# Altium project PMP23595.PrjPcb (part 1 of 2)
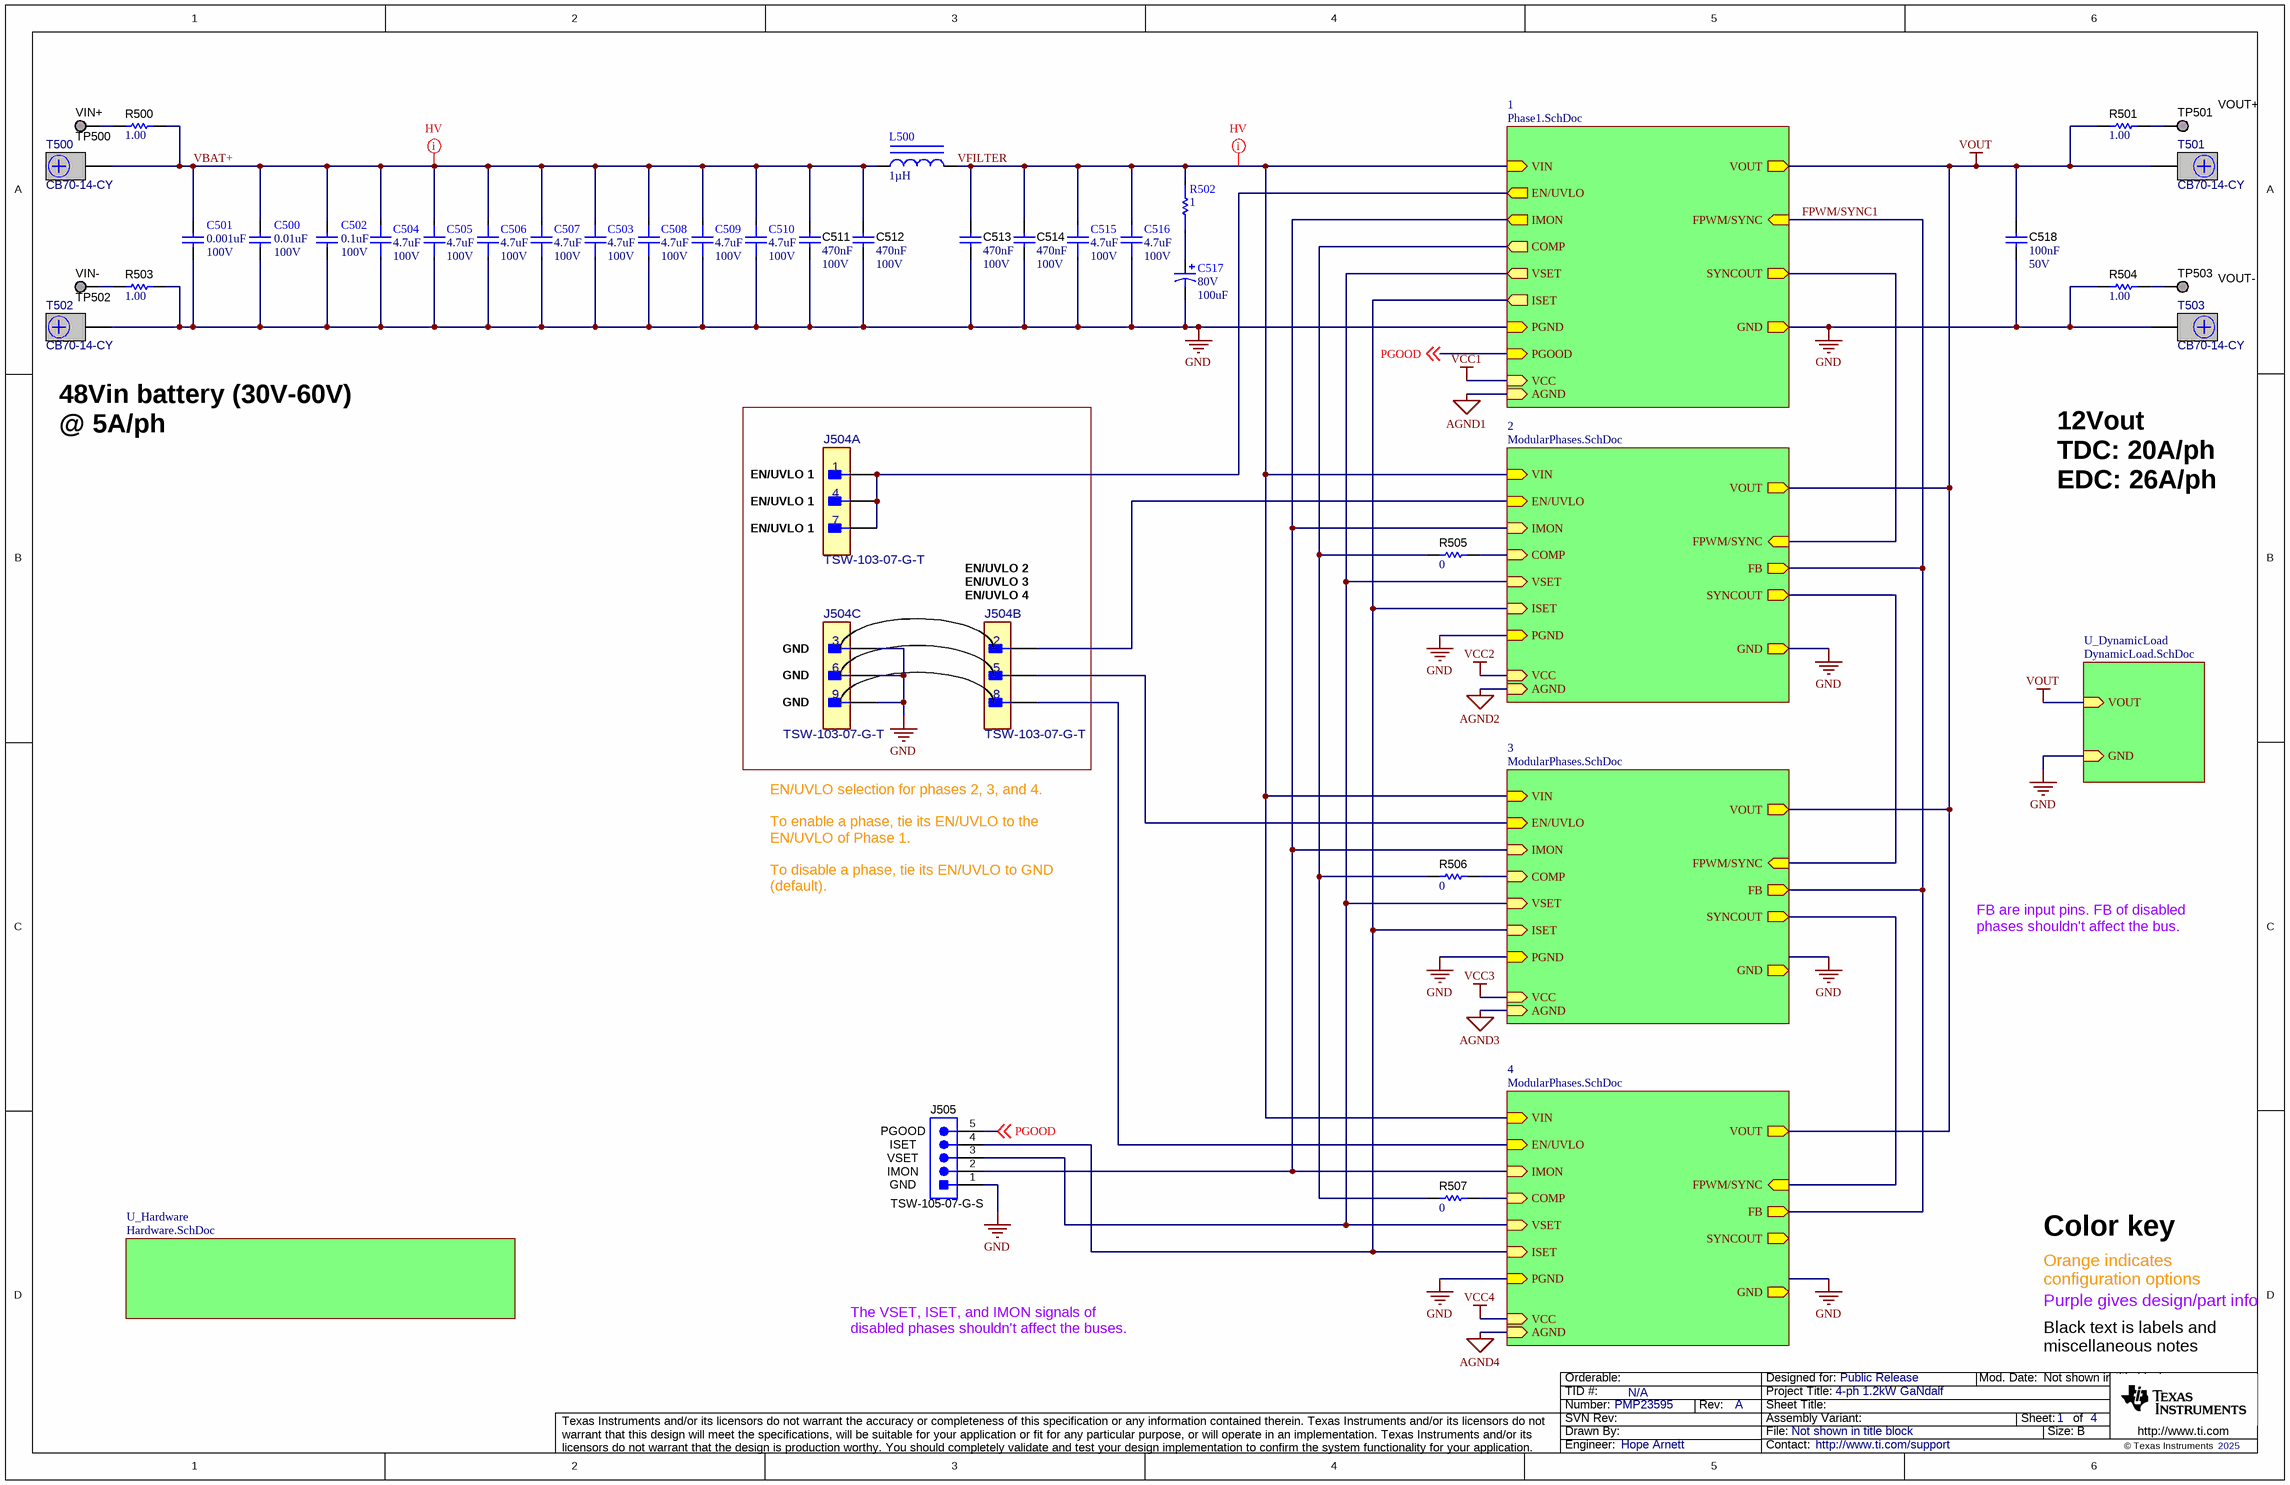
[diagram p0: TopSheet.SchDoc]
CopyrightYear: 2025; PCB_Layout: Hope Arnett; PCB_Rev: A; PRJ_Customer: Public Release; PRJ_Engineer: Hope Arnett; PRJ_Number: PMP23595; PRJ_Title: 4-ph 1.2kW GaNdalf; SCH_Rev: A; TechSupport: http://www.ti.com/support; TID: N/A
5 sheets, 237 parts. Net scope: hierarchical (ports join the sheet entries above them; power ports are global).
Board file: PMP23595.PcbDoc
Sheets:
  TopSheet.SchDoc
    U_Hardware = Hardware.SchDoc
    2 = ModularPhases.SchDoc
    1 = Phase1.SchDoc
    U_DynamicLoad = DynamicLoad.SchDoc
    3 = ModularPhases.SchDoc
    4 = ModularPhases.SchDoc

## Sheet TopSheet.SchDoc
size 431 x 279 mm; Date: Not shown in title block; ApprovedBy: Not shown in title block; CheckedBy: Not shown in title block; Author: Not shown in title block; CompanyName: Not shown in title block; Engineer: Not shown in title block; Organization: Not shown in title block; Address1: Not shown in title block; Address2: Not shown in title block; Address3: Not shown in title block; Address4: Not shown in title block; DocumentNumber: 1; Revision: Use project parameter SCH_Rev; SheetNumber: 1; SheetTotal: 4; PageSetup: Record=PageOptions¦CenterHorizontal=True¦CenterVertical=True¦PrintScale=1.00¦XCorrection=1.00¦YCorrection=1.00¦PrintKind=0¦BorderSize=5000000¦LeftOffset=0¦BottomOffset=0¦Orientation=2¦PaperLength=1000¦PaperWidth=1000¦Scale=100¦PaperSource=15¦PrintQuality=600¦MediaType=1¦DitherType=10¦PaperKind=Letter¦PrintScaleMode=1

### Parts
C500  Value2: 100V  ValueDisplayed: 0.01uF  [0603L]  (hidden comment: GRM188R72A103KA01D)
C501  Cap_F: 0.001uF  VDC_V: 100V  [0603L]  (hidden comment: CGA3E2X7R2A102K080AA)
C502  Value2: 100V  ValueDisplayed: 0.1uF  [0805]  (hidden comment: C0805C104K1RACTU)
C503  ValueDisplayed: 4.7uF  VDC_V: 100V  [FP-GCJ32DC72A475KE01L_1210-MFG]  (hidden comment: GCJ32DC72A475KE01L)
C504  ValueDisplayed: 4.7uF  VDC_V: 100V  [FP-GCJ32DC72A475KE01L_1210-MFG]  (hidden comment: GCJ32DC72A475KE01L)
C505  ValueDisplayed: 4.7uF  VDC_V: 100V  [FP-GCJ32DC72A475KE01L_1210-MFG]  (hidden comment: GCJ32DC72A475KE01L)
C506  ValueDisplayed: 4.7uF  VDC_V: 100V  [FP-GCJ32DC72A475KE01L_1210-MFG]  (hidden comment: GCJ32DC72A475KE01L)
C507  ValueDisplayed: 4.7uF  VDC_V: 100V  [FP-GCJ32DC72A475KE01L_1210-MFG]  (hidden comment: GCJ32DC72A475KE01L)
C508  ValueDisplayed: 4.7uF  VDC_V: 100V  [FP-GCJ32DC72A475KE01L_1210-MFG]  (hidden comment: GCJ32DC72A475KE01L)
C509  ValueDisplayed: 4.7uF  VDC_V: 100V  [FP-GCJ32DC72A475KE01L_1210-MFG]  (hidden comment: GCJ32DC72A475KE01L)
C510  ValueDisplayed: 4.7uF  VDC_V: 100V  [FP-GCJ32DC72A475KE01L_1210-MFG]  (hidden comment: GCJ32DC72A475KE01L)
C511  Cap_F: 470nF  VDC_V: 100V  [0805L]  (hidden comment: GRM21BR72A474KA73L)
C512  Cap_F: 470nF  VDC_V: 100V  [0805L]  (hidden comment: GRM21BR72A474KA73L)
C513  Cap_F: 470nF  VDC_V: 100V  [0805L]  (hidden comment: GRM21BR72A474KA73L)
C514  Cap_F: 470nF  VDC_V: 100V  [0805L]  (hidden comment: GRM21BR72A474KA73L)
C515  ValueDisplayed: 4.7uF  VDC_V: 100V  [FP-GCJ32DC72A475KE01L_1210-MFG]  (hidden comment: GCJ32DC72A475KE01L)
C516  ValueDisplayed: 4.7uF  VDC_V: 100V  [FP-GCJ32DC72A475KE01L_1210-MFG]  (hidden comment: GCJ32DC72A475KE01L)
C517  VDC_V: 80V  ValueDisplayed: 100uF  [SM_RADIAL_H13]  (hidden comment: EEV-FK1K101Q)
C518  Cap_F: 100nF  VDC_V: 50V  [0603L]  (hidden comment: 06035C104KAZ2A)
J504  TSW-103-07-G-T  [FP-TSW-103-07-G-T_HDR9-MFG]  (parts A,B,C of 3)
J505  TSW-105-07-G-S  [TSW-105-07-X-S]
L500  ValueDisplayed: 1µH  [VCHA105D]  (hidden comment: VCHA105D-1R0MS6)
R500  ValueDisplayed: 1.00  [0603L]  (hidden comment: CRCW06031R00FKEA)
R501  ValueDisplayed: 1.00  [0603L]  (hidden comment: CRCW06031R00FKEA)
R502  value 1  [FP-RCL12251R00FKEG_2512-MFG]  (hidden comment: RCL12251R00FKEG)
R503  ValueDisplayed: 1.00  [0603L]  (hidden comment: CRCW06031R00FKEA)
R504  ValueDisplayed: 1.00  [0603L]  (hidden comment: CRCW06031R00FKEA)
R505  ValueDisplayed: 0  [0402L]  (hidden comment: RK73Z1ETTP)
R506  ValueDisplayed: 0  [0402L]  (hidden comment: RK73Z1ETTP)
R507  ValueDisplayed: 0  [0402L]  (hidden comment: RK73Z1ETTP)
T500  CB70-14-CY  [CB70-14-CY]
T501  CB70-14-CY  [CB70-14-CY]
T502  CB70-14-CY  [CB70-14-CY]
T503  CB70-14-CY  [CB70-14-CY]
TP500  VIN+  [Keystone_5019]
TP501  VOUT+  [Keystone_5019]
TP502  VIN-  [Keystone_5019]
TP503  VOUT-  [Keystone_5019]

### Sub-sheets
1 = Phase1.SchDoc: VIN (in), PGND (in), VOUT (out), GND (out), EN/UVLO (out), SYNCOUT (out), COMP (out), AGND (in), VCC (in), IMON (out), ISET (out), VSET (out), FPWM/SYNC (in), PGOOD (in)
2 = ModularPhases.SchDoc: VIN (in), PGND (in), VOUT (out), GND (out), FPWM/SYNC (in), SYNCOUT (out), COMP (in), AGND (in), VCC (in), EN/UVLO (in), IMON (in), VSET (in), ISET (in), FB (out)
3 = ModularPhases.SchDoc: VIN (in), PGND (in), VOUT (out), GND (out), FPWM/SYNC (in), SYNCOUT (out), COMP (in), AGND (in), VCC (in), EN/UVLO (in), IMON (in), VSET (in), ISET (in), FB (out)
4 = ModularPhases.SchDoc: VIN (in), PGND (in), VOUT (out), GND (out), FPWM/SYNC (in), SYNCOUT (out), COMP (in), AGND (in), VCC (in), EN/UVLO (in), IMON (in), VSET (in), ISET (in), FB (out)
U_DynamicLoad = DynamicLoad.SchDoc: VOUT (in), GND (in)
U_Hardware = Hardware.SchDoc: no entries

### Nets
AGND1: sheet 2/AGND, sheet 1/AGND, sheet 3/AGND, sheet 4/AGND  [also labelled AGND2, AGND3, AGND4]
GND: C500.1 C501.2 C502.2 C503.1 C504.1 C505.1 C506.1 C507.1 C508.1 C509.1 C510.1 C511.2 C512.2 C513.2 C514.2 C515.1 C516.1 C517.2(-) C518.2 J504.3 J504.6 J504.9 J505.1 R503.2 R504.1 T502.1 T503.1 ; sheet 2/PGND, sheet 2/GND, sheet 1/PGND, sheet 1/GND, sheet U_DynamicLoad/GND, sheet 3/PGND, sheet 3/GND, sheet 4/PGND, sheet 4/GND
VCC1: sheet 2/VCC, sheet 1/VCC, sheet 3/VCC, sheet 4/VCC  [also labelled VCC2, VCC3, VCC4]
VFILTER: C513.1 C514.1 C515.2 C516.2 L500.2 R502.2 ; sheet 2/VIN, sheet 1/VIN, sheet 3/VIN, sheet 4/VIN
VOUT: C518.1 R501.1 T501.1 ; sheet 2/VOUT, sheet 1/VOUT, sheet U_DynamicLoad/VOUT, sheet 3/VOUT, sheet 4/VOUT
COMP: R505.2 R506.2 R507.2 ; sheet 1/COMP
COMP: R507.1 ; sheet 4/COMP  [a separate net that carries the same name]
COMP: R506.1 ; sheet 3/COMP  [a separate net that carries the same name]
COMP: R505.1 ; sheet 2/COMP  [a separate net that carries the same name]
EN/UVLO: J504.1 J504.4 J504.7 ; sheet 1/EN/UVLO
EN/UVLO: J504.2 ; sheet 2/EN/UVLO  [a separate net that carries the same name]
EN/UVLO: J504.5 ; sheet 3/EN/UVLO  [a separate net that carries the same name]
EN/UVLO: J504.8 ; sheet 4/EN/UVLO  [a separate net that carries the same name]
FPWM/SYNC: sheet 2/FPWM/SYNC, sheet 1/SYNCOUT
FPWM/SYNC: sheet 2/SYNCOUT, sheet 3/FPWM/SYNC  [a separate net that carries the same name]
FPWM/SYNC: sheet 3/SYNCOUT, sheet 4/FPWM/SYNC  [a separate net that carries the same name]
FPWM/SYNC1: sheet 2/FB, sheet 1/FPWM/SYNC, sheet 3/FB, sheet 4/FB
IMON: J505.2 ; sheet 2/IMON, sheet 1/IMON, sheet 3/IMON, sheet 4/IMON
ISET: J505.4 ; sheet 2/ISET, sheet 1/ISET, sheet 3/ISET, sheet 4/ISET
PGOOD: J505.5 ; off-sheet PGOOD, sheet 1/PGOOD
VBAT+: C500.2 C501.1 C502.1 C503.2 C504.2 C505.2 C506.2 C507.2 C508.2 C509.2 C510.2 C511.1 C512.1 L500.1 R500.2 T500.1
VSET: J505.3 ; sheet 2/VSET, sheet 1/VSET, sheet 3/VSET, sheet 4/VSET
NetC517_1: C517.1(+) R502.1
NetR500_1: R500.1 TP500.1
NetR501_2: R501.2 TP501.1
NetR503_1: R503.1 TP502.1
NetR504_2: R504.2 TP503.1

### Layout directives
net class HV: VBAT+, VFILTER

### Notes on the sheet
- (near T502) 48Vin battery (30V-60V) @ 5A/ph
- (near J504) EN/UVLO 1
- 12Vout
  TDC: 20A/ph
  EDC: 26A/ph
- EN/UVLO 2
- EN/UVLO 3
- (near J504) EN/UVLO 4
- (near J504) GND
- EN/UVLO selection for phases 2, 3, and 4.
  To enable a phase, tie its EN/UVLO to the EN/UVLO of Phase 1.
  To disable a phase, tie its EN/UVLO to GND (default).
- FB are input pins. FB of disabled phases shouldn't affect the bus.
- (near J505) IMON
- (near J505) VSET
- (near J505) ISET
- (near J505) PGOOD
- (near J505) GND
- Orange indicates configuration options
- Color key
- The VSET, ISET, and IMON signals of disabled phases shouldn't affect the buses.
- Purple gives design/part info
- Black text is labels and miscellaneous notes

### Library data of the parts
C500 = CMP-0007468-5: CAP, CERM, 0.01 uF, 100 V, +/- 10%, X7R, 0603; Manufacturer: MuRata; TaMin_C: -55°C; Polarized: N; SizeAreaWB_mm2: 4.68; Value1: Unknown; U/M: EA; Value: 0.01uF; TaMax_C: 125°C; SizeZ_mm: 1; SizeX_mm: 1.6; SizeY_mm: 0.8; Cap_Case: 0603; SizeArea_mm2: 1.28; Cap_F: 10nF; AEC Category: Q200
C501 = CMP-0007081-4: CAP, CERM, 1000 pF, 100 V, +/- 10%, X7R, AEC-Q200 Grade 1, 0603; Manufacturer: TDK; TaMin_C: -55°C; ESR_ohm: 1.9714; Polarized: N; SizeAreaWB_mm2: 4.68; Value1: 1.97137 ohm; U/M: EA; Value: 1000pF; TaMax_C: 125°C; SizeZ_mm: 1; SizeX_mm: 1.6; SizeY_mm: 0.8; Cap_Case: 0603; SizeArea_mm2: 1.28; AEC Qualified: Y; IRMS_A: 305.705mA; AEC Category: Q200
C502 = CMP-0007722-2: CAP, CERM, 0.1 uF, 100 V, +/- 10%, X7R, 0805; Manufacturer: Kemet; TaMin_C: -55°C; ESR_ohm: 64m; Polarized: N; SizeAreaWB_mm2: 6.75; Value1: 0.064 ohm; U/M: EA; Value: 0.1uF; TaMax_C: 125°C; SizeZ_mm: 1.45; SizeX_mm: 2; SizeY_mm: 1.25; SizeArea_mm2: 2.5; Cap_F: 100nF; IRMS_A: 1.64A; AEC Category: Q200
C503-C510 C515 C516 = CMP-0093675-1: 4.7uF ±10% 100V Ceramic Capacitor X7S 1210 (3225 Metric); Manufacturer: Murata; Value: 4.7µF; AEC Qualified: Yes; TempCo: 22%; SizeZ_mm: 2.3mm; AEC Grade: Grade 1
C511-C514 = CMP-0008374-2: CAP, CERM, 0.47 uF, 100 V, +/- 10%, X7R, 0805; Manufacturer: MuRata; TaMin_C: -55°C; Polarized: N; SizeAreaWB_mm2: 6.75; Value1: Unknown; U/M: EA; Value: 0.47uF; TaMax_C: 125°C; SizeZ_mm: 1.45; SizeX_mm: 2; SizeY_mm: 1.25; Cap_Case: 0805; SizeArea_mm2: 2.5; AEC Category: Q200
C517 = CMP-0011216-2: CAP, AL, 100 uF, 80 V, +/- 20%, 0.32 ohm, AEC-Q200 Grade 2, SMD; Manufacturer: Panasonic; TaMin_C: -55°C; ESR_ohm: 0.32; Polarized: Y; SizeAreaWB_mm2: 263.5; U/M: EA; Value: 100uF; TaMax_C: 105°C; SizeZ_mm: 13.5; SizeX_mm: 15; Cap_Case: H13; SizeArea_mm2: 202.5; CompType: Capacitor; Cap_F: 100µF; IRMS_A: 500mA; AEC Grade: 2; AEC Category: Q200
C518 = CMP-0079095-1: CAP, CERM, 0.1 µF, 50 V,+/- 10%, X7R, AEC-Q200 Grade 1, 0603; Manufacturer: AVX; SizeAreaWB_mm2: 4.68; SizeArea_mm2: 1.28; AEC Qualified: Y; AEC Category: Q200; Value: 0.1uF; TaMax_C: 125°C; SizeZ_mm: 1; Polarized: N; TaMin_C: -55°C; SizeY_mm: 0.8; U/M: EA; SizeX_mm: 1.6; Cap_Case: 0603; ValueDisplayed: 0.1µF
J504 = CMP-0090263-1: Connector Header Through Hole 9 position 0.100" (2.54mm); Manufacturer: Samtec; Conn Gender: Male; AEC Qualified: No; Conn Orientation: Straight; Row_Count: 3; SizeZ_mm: 8.64mm; ContactFinish: Gold,Nickel
J505 = CMP-0075411-1: Header, 100mil, 5x1, Gold, TH; Manufacturer: Samtec; Pitch_mm: 2.54; Cert_VDE: N; Gender: Male; Cert_CSA: Y; Voltage_V: 550V; Green_REACh: Passed; Current_A: 6.3A; CT: False; Green_Lifecycle: Active; Row_Count: 1; CNHeader: True
L500 = CMP-0086238-1: Inductor, 1 µH, 30 A, 0.00276 ohm, AEC-Q200 Grade 0, SMD; Manufacturer: Cyntec; AEC Category: Q200; AEC Grade: 0; Value: 1uH; AEC Qualified: Y; Irms: 30A @ 40C rise; Isat: 37A @ 30% inductance drop; DCR_ohm: 2.76m; SizeX_mm: 10.85; Imax_A: 30A; SizeArea_mm2: 108.5; SizeZ_mm: 5.4; SizeAreaWB_mm2: 154.2; SizeY_mm: 10
R500 R501 R503 R504 = CMP-0022170-4: RES, 1.00, 1%, 0.1 W, AEC-Q200 Grade 0, 0603; Manufacturer: Vishay-Dale; Power_W: 100mW; TempCo: 100 ppm/C; Value_Code: 1R00; Value: 1.00; EIA_Code: E96; Res_ohm: 1; SizeX_mm: 1.6; SizeY_mm: 0.8; Value2: 0.1W; SizeArea_mm2: 1.28; AEC Qualified: Y; VDC_V: 75V; AEC Category: Q200; AEC Grade: 0
R502 = CMP-0084352-2: 1 Ohms ±1% 2W Chip Resistor Wide 2512 (6432 Metric), 1225 Automotive AEC-Q200 Thick Film; Manufacturer: Vishay Dale; SizeZ_mm: 0.8mm; Symbol Name: SYM-RCL12251R00FKEG; TempCo: 100ppm/°C; VDC_V: 200V; AEC Qualified: Yes; AEC Grade: Grade 0
R505-R507 = CMP-0027007-2: RES, 0, 5%, 0.063 W, AEC-Q200 Grade 0, 0402; Manufacturer: KOA Speer; Power_W: 63mW; TempCo: ppm/C; Value_Code: 0000; U/M: EA; Value: 0; EIA_Code: E24; SizeX_mm: 1; SizeY_mm: 0.5; SizeZ_mm: 0.6; Value2: 0.063W; AEC Qualified: Y; AEC Category: Q200
T500-T503 = CMP-0055443-2: Terminal 90A Lug; Manufacturer: Panduit; Green_Lifecycle: Not Set; Cert_CULUS: Y; Green_REACh: Incomplete; Voltage_V: 600V; CompType: Screw Terminal; ContactFinish: Copper
TP500-TP503 = CMP-0055162-1: Test Point, Miniature, SMT; Manufacturer: Keystone; PartNumber: 5019; CNHeader: FALSE; Green_Lifecycle: Active; Green_REACh: Passed; CT: TRUE

## Sheet Hardware.SchDoc
size 431 x 279 mm; Date: Not shown in title block; ApprovedBy: Not shown in title block; CheckedBy: Not shown in title block; Author: Not shown in title block; CompanyName: Not shown in title block; Engineer: Not shown in title block; Organization: Not shown in title block; Address1: Not shown in title block; Address2: Not shown in title block; Address3: Not shown in title block; Address4: Not shown in title block; DocumentNumber: 4; Revision: Use project parameter SCH_Rev; SheetNumber: 4; SheetTotal: 4; PageSetup: Record=PageOptions¦CenterHorizontal=True¦CenterVertical=True¦PrintScale=1.00¦XCorrection=1.00¦YCorrection=1.00¦PrintKind=0¦BorderSize=5000000¦LeftOffset=0¦BottomOffset=0¦Orientation=2¦PaperLength=1000¦PaperWidth=1000¦Scale=100¦PaperSource=15¦PrintQuality=600¦MediaType=1¦DitherType=10¦PaperKind=Letter¦PrintScaleMode=1
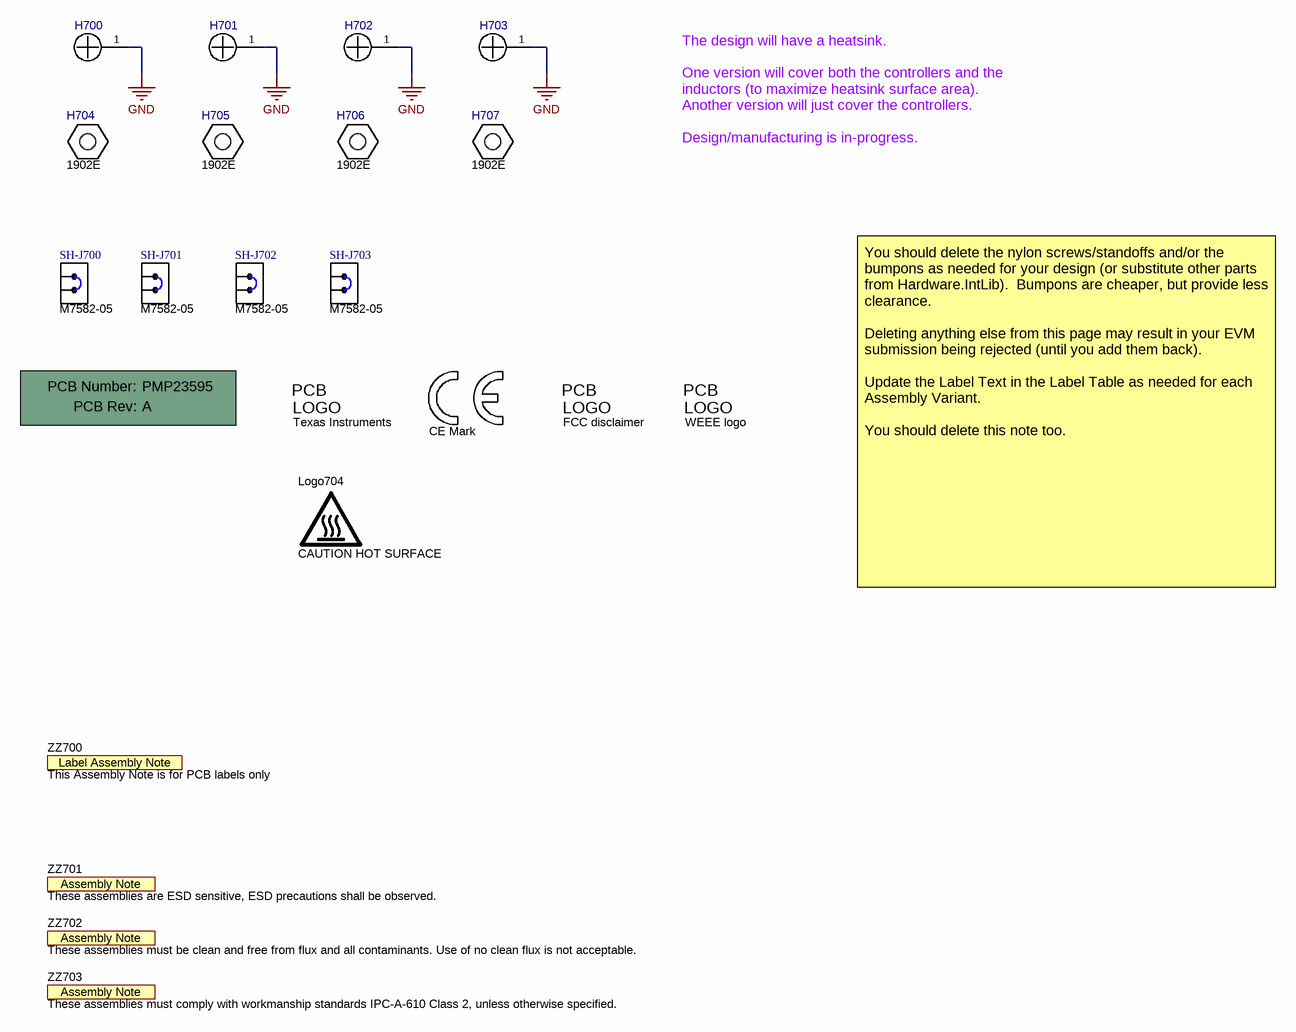
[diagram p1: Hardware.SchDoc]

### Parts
!PCB700  Printed Circuit Board  (value not drawn)  (mechanical)
H700  NY PMS 440 0025 PH  [NY PMS 440 0025 PH]  (value not drawn)
H701  NY PMS 440 0025 PH  [NY PMS 440 0025 PH]  (value not drawn)
H702  NY PMS 440 0025 PH  [NY PMS 440 0025 PH]  (value not drawn)
H703  NY PMS 440 0025 PH  [NY PMS 440 0025 PH]  (value not drawn)
H704  1902E  [Keystone_1902E]
H705  1902E  [Keystone_1902E]
H706  1902E  [Keystone_1902E]
H707  1902E  [Keystone_1902E]
Logo700  CE Mark  [CE_Mark_5mm]  (no BOM)
Logo701  Texas Instruments  [TI_Stacked_Overlay_Small]  (no BOM)
Logo702  FCC disclaimer  [FCC_disclaimer]  (no BOM)
Logo703  WEEE logo  [WEEE_Minimum]  (no BOM)
Logo704  CAUTION HOT SURFACE  [IEC_HotSurface_Small]  (no BOM)
SH-J700  M7582-05  [Harwin_M7582-05]
SH-J701  M7582-05  [Harwin_M7582-05]
SH-J702  M7582-05  [Harwin_M7582-05]
SH-J703  M7582-05  [Harwin_M7582-05]
ZZ700  This Assembly Note is for PCB labels only  [AssemblyNoteLabel]  (no BOM)
ZZ701  These assemblies are ESD sensitive, ESD precautions shall be observed.  [AssemblyNote]  (no BOM)
ZZ702  These assemblies must be clean and free from flux and all contaminants. Use of no clean flux is not acceptable.  [AssemblyNote]  (no BOM)
ZZ703  These assemblies must comply with workmanship standards IPC-A-610 Class 2, unless otherwise specified.  [AssemblyNote]  (no BOM)

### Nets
GND: H700.1 H701.1 H702.1 H703.1

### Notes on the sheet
- The design will have a heatsink.
  One version will cover both the controllers and the inductors (to maximize heatsink surface area). Another version will just cover the controllers.
  Design/manufacturing is in-progress.
- You should delete the nylon screws/standoffs and/or the bumpons as needed for your design (or substitute other parts from Hardware.IntLib).  Bumpons are cheaper, but provide less clearance.
  Deleting anything else from this page may result in your EVM submission being rejected (until you add them back).
  Update the Label Text in the Label Table as needed for each Assembly Variant.
  You should delete this note too.

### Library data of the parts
!PCB700 = CMP-0003618-2: Manufacturer: Any; PartNumber: PMP23595
H700-H703 = CMP-0003617-1: Machine Screw, Round, #4-40 x 1/4, Nylon, Philips panhead; Manufacturer: B&F Fastener Supply; CompType: Hardware
H704-H707 = CMP-0003611-1: Standoff, Hex, 1"L #4-40 Nylon; Manufacturer: Keystone; CompType: Hardware
Logo700 = CMP-0074844-1: SymbolCreator: a0412235
Logo701 = CMP-0074838-1: Texas Instrument Corporate Signature; SymbolCreator: a0412235; Lib Reference: TI_Logo; Library Reference: Logo
Logo702 = CMP-0074847-1: FCC_disclaimer; Library Reference: Logo
Logo703 = CMP-0074769-1
Logo704 = CMP-0074837-2: IEC 61010-1 Hot Surface Warning; Manufacturer: Texas Instruments; CompType: IC; AEC Category: Q200; SymbolCreator: a0412235
SH-J700-SH-J703 = CMP-0078738-1: Single Operation 2.54mm Pitch Open Top Jumper Socket; Manufacturer: Harwin
ZZ700 = CMP-0003616-3
ZZ701 = CMP-0077236-1
ZZ702 = CMP-0077237-1
ZZ703 = CMP-0077238-1

## Sheet ModularPhases.SchDoc
size 431 x 279 mm; Date: Not shown in title block; ApprovedBy: Not shown in title block; CheckedBy: Not shown in title block; Author: Not shown in title block; CompanyName: Not shown in title block; Engineer: Not shown in title block; Organization: Not shown in title block; Address1: Not shown in title block; Address2: Not shown in title block; Address3: Not shown in title block; Address4: Not shown in title block; DocumentNumber: 3; Revision: Use project parameter SCH_Rev; SheetNumber: 3; SheetTotal: 4; PageSetup: Record=PageOptions¦CenterHorizontal=True¦CenterVertical=True¦PrintScale=1.00¦XCorrection=1.00¦YCorrection=1.00¦PrintKind=0¦BorderSize=5000000¦LeftOffset=0¦BottomOffset=0¦Orientation=2¦PaperLength=1000¦PaperWidth=1000¦Scale=100¦PaperSource=15¦PrintQuality=600¦MediaType=1¦DitherType=10¦PaperKind=Letter¦PrintScaleMode=1
Used 3 times, as channels 2, 3, 4. Parts and nets are listed once, with the designators drawn on the sheet.
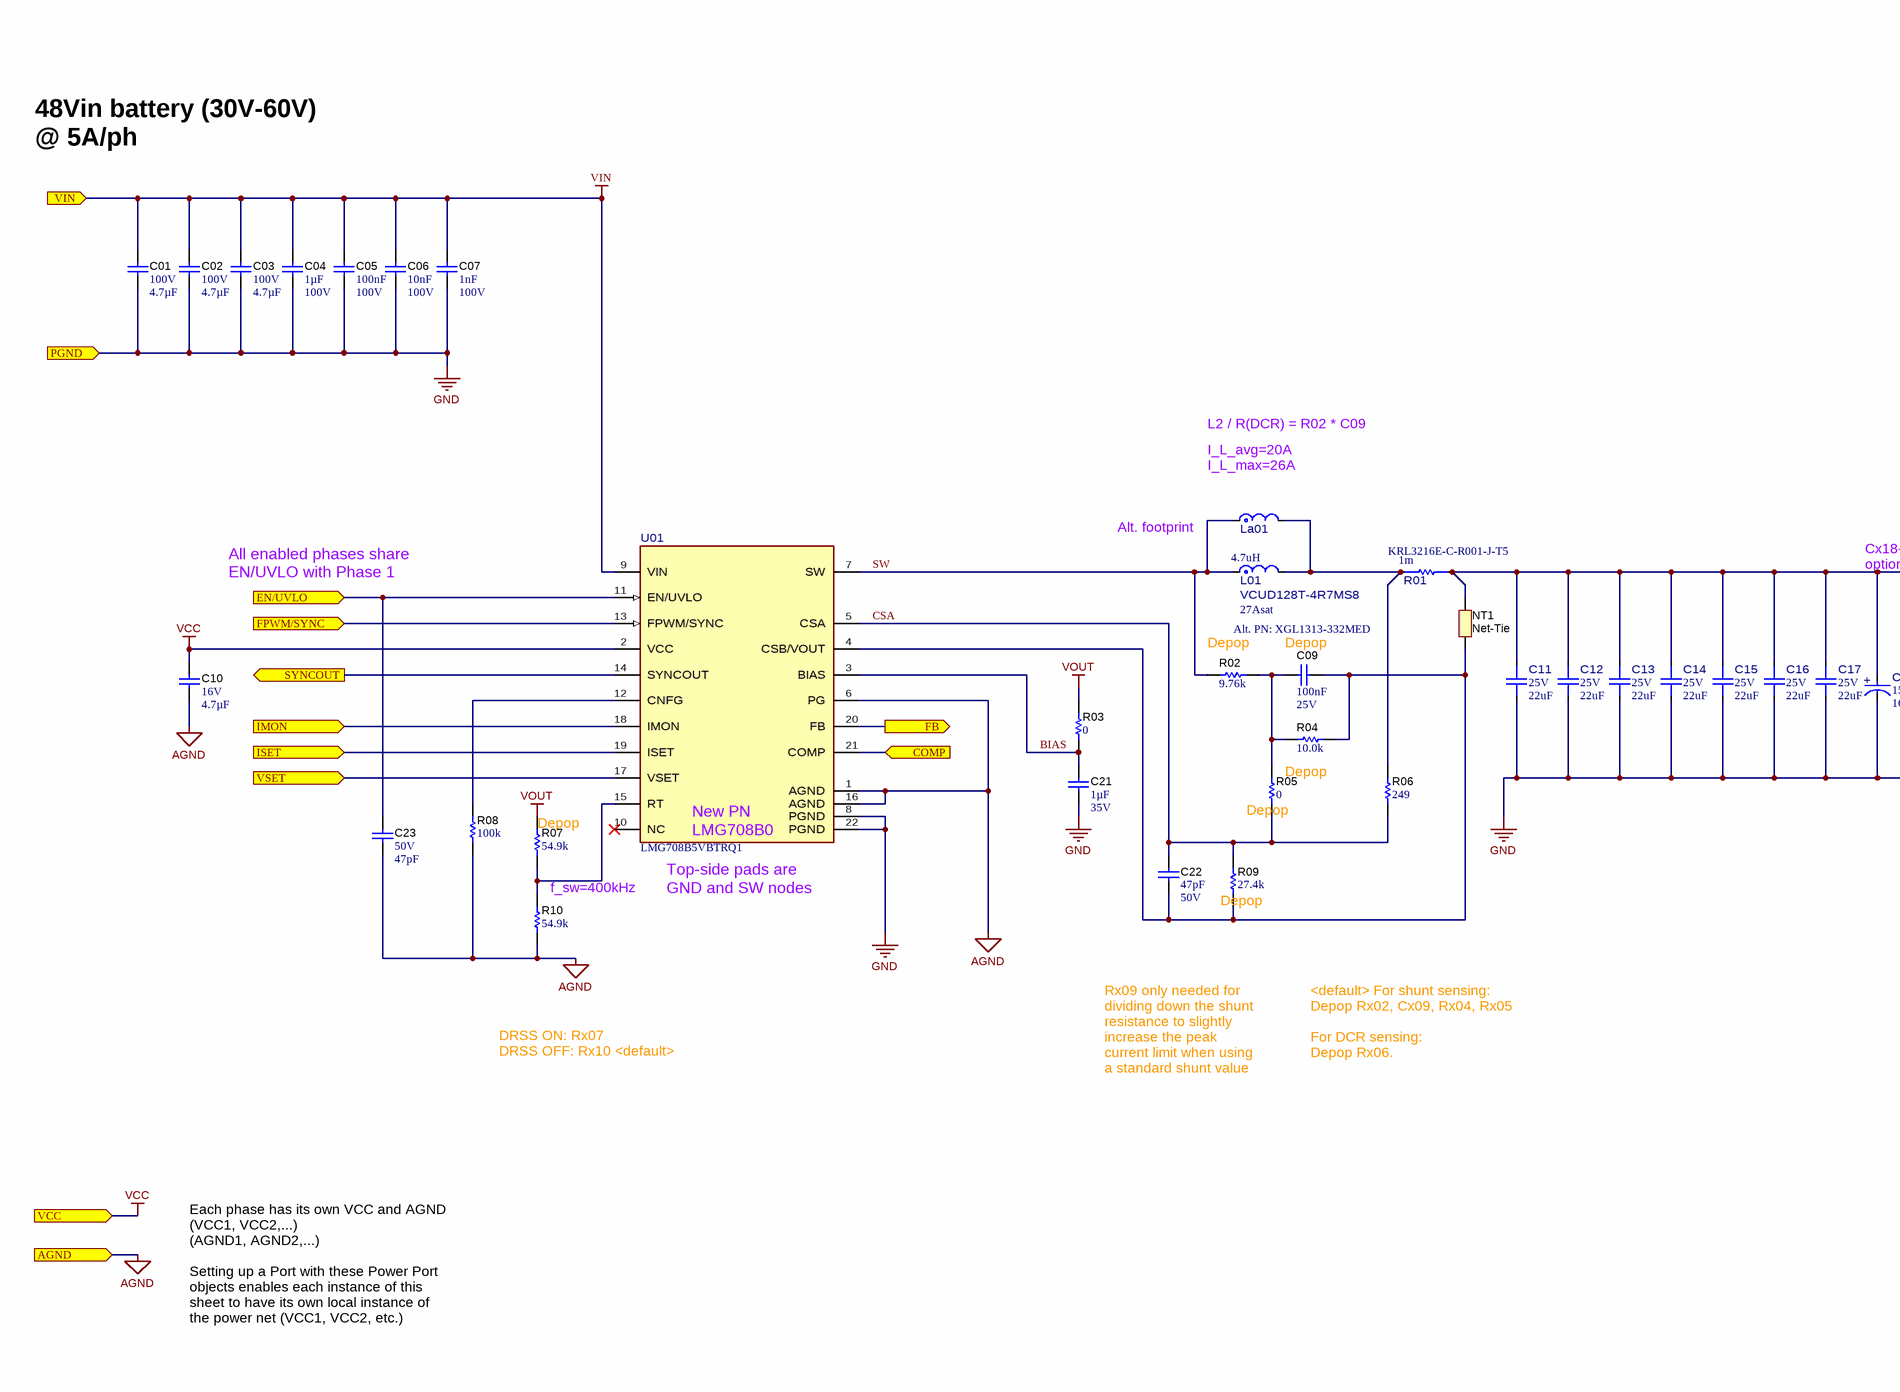
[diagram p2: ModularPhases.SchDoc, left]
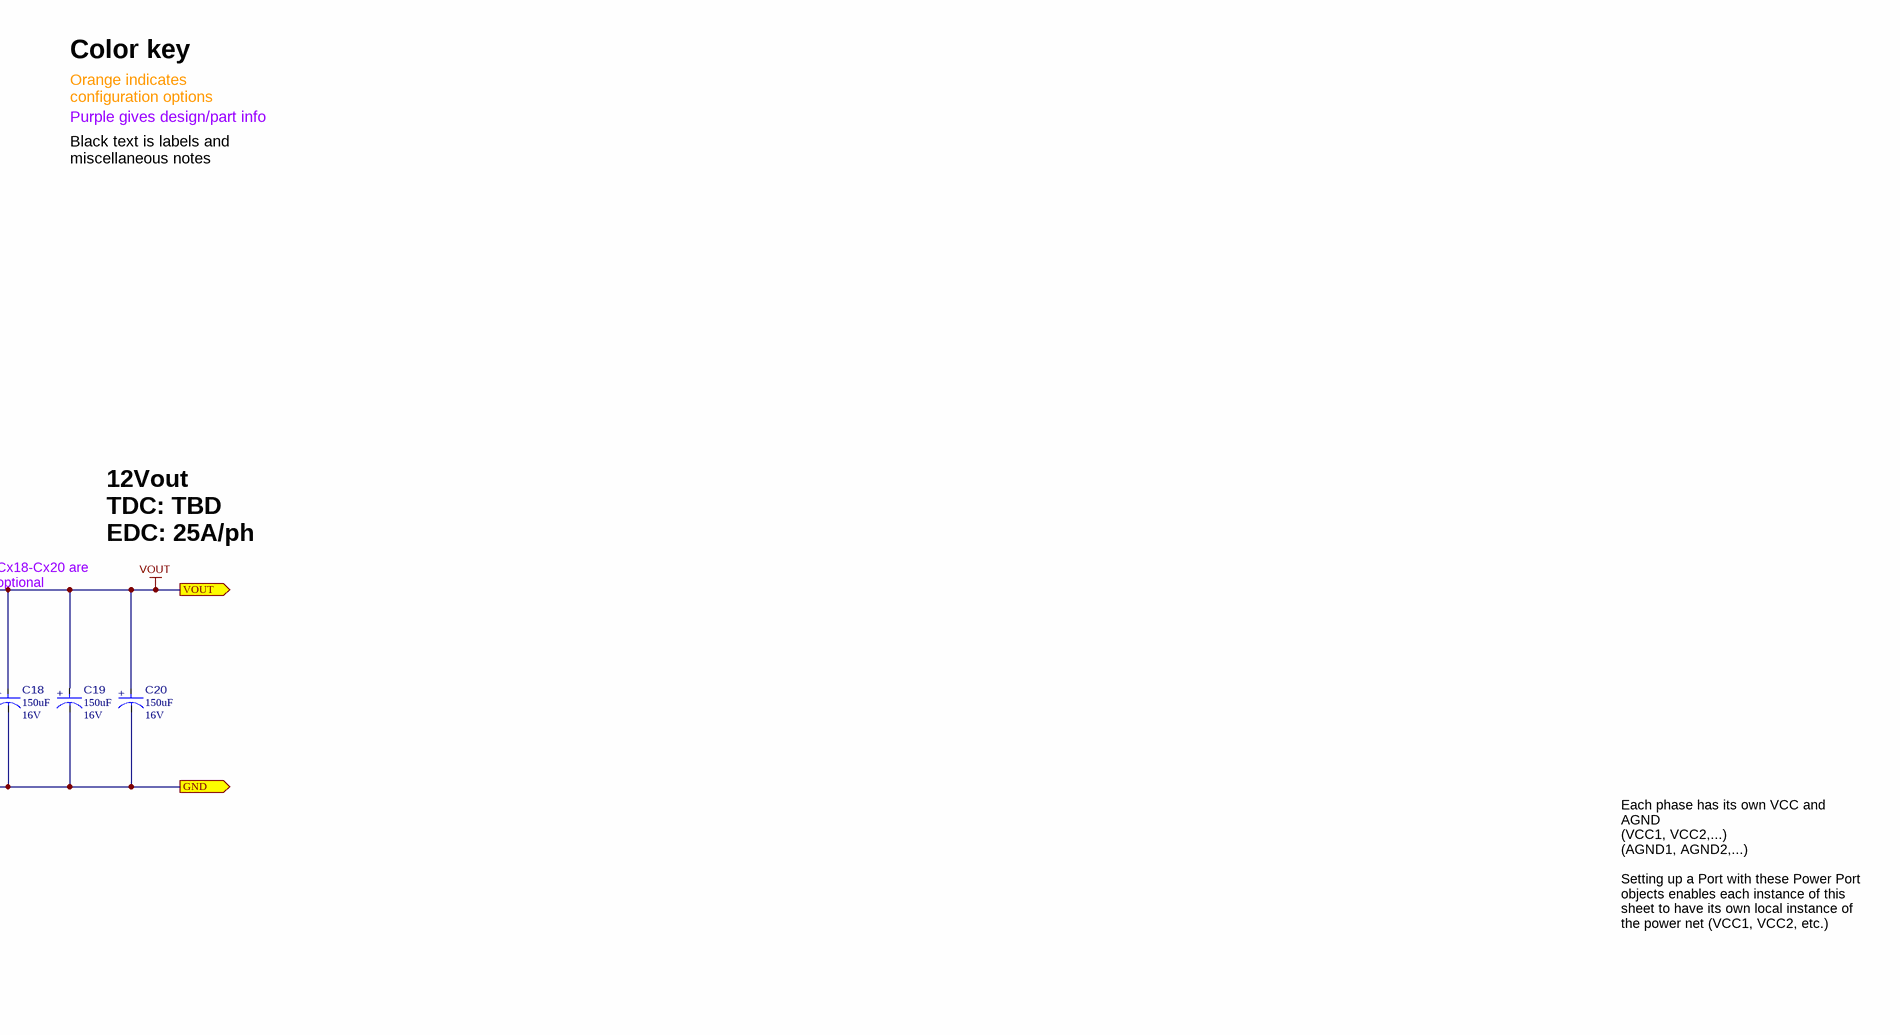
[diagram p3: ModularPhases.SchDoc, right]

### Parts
C01  VDC_V: 100V  ValueDisplayed: 4.7µF  [1210_220]  (hidden comment: GCM32DC72A475KE02L)
C02  VDC_V: 100V  ValueDisplayed: 4.7µF  [1210_220]  (hidden comment: GCM32DC72A475KE02L)
C03  VDC_V: 100V  ValueDisplayed: 4.7µF  [1210_220]  (hidden comment: GCM32DC72A475KE02L)
C04  Cap_F: 1µF  VDC_V: 100V  [0805L]  (hidden comment: CGA4J3X7S2A105K125AB)
C05  Cap_F: 100nF  VDC_V: 100V  [0603L]  (hidden comment: HMK107B7104MAHT)
C06  Cap_F: 10nF  VDC_V: 100V  [0402L]  (hidden comment: CGA2B3X7S2A103K050BB)
C07  Cap_F: 1nF  VDC_V: 100V  [0402L]  (hidden comment: CGA2B3X7S2A102K050BB)
C09  Cap_F: 100nF  VDC_V: 25V  [0402L]  (hidden comment: CGA2B3X7R1E104K050BB)
C10  VDC_V: 16V  ValueDisplayed: 4.7µF  [0603L]  (hidden comment: GRT188R61C475KE13D)
C11  VDC_V: 25V  ValueDisplayed: 22uF  [FP-GCM32EC71E226KE36L_1210-MFG]  (hidden comment: GCM32EC71E226KE36L)
C12  VDC_V: 25V  ValueDisplayed: 22uF  [FP-GCM32EC71E226KE36L_1210-MFG]  (hidden comment: GCM32EC71E226KE36L)
C13  VDC_V: 25V  ValueDisplayed: 22uF  [FP-GCM32EC71E226KE36L_1210-MFG]  (hidden comment: GCM32EC71E226KE36L)
C14  VDC_V: 25V  ValueDisplayed: 22uF  [FP-GCM32EC71E226KE36L_1210-MFG]  (hidden comment: GCM32EC71E226KE36L)
C15  VDC_V: 25V  ValueDisplayed: 22uF  [FP-GCM32EC71E226KE36L_1210-MFG]  (hidden comment: GCM32EC71E226KE36L)
C16  VDC_V: 25V  ValueDisplayed: 22uF  [FP-GCM32EC71E226KE36L_1210-MFG]  (hidden comment: GCM32EC71E226KE36L)
C17  VDC_V: 25V  ValueDisplayed: 22uF  [FP-GCM32EC71E226KE36L_1210-MFG]  (hidden comment: GCM32EC71E226KE36L)
C18  ValueDisplayed: 150uF  VDC_V: 16V  [FP-TCQE157M016R0025E_2917-MFG]  (hidden comment: TCQE157M016R0025E)
C19  ValueDisplayed: 150uF  VDC_V: 16V  [FP-TCQE157M016R0025E_2917-MFG]  (hidden comment: TCQE157M016R0025E)
C20  ValueDisplayed: 150uF  VDC_V: 16V  [FP-TCQE157M016R0025E_2917-MFG]  (hidden comment: TCQE157M016R0025E)
C21  Cap_F: 1µF  VDC_V: 35V  [0603L]  (hidden comment: CGA3E1X7R1V105K080AE)
C22  ValueDisplayed: 47pF  VDC_V: 50V  [0402L]  (hidden comment: CGA2B2C0G1H470J050BA)
C23  VDC_V: 50V  ValueDisplayed: 47pF  [0402L]  (hidden comment: CGA2B2NP01H470J050BA)
L01  VCUD128T-4R7MS8  value 4.7uH  [FP-VCUD128T-4R7MS8_SMT_IND_13MM3_12MM8-MFG]
La01  VCHA105D-4R7MS6  [FP-VCHA105D-4R7MS6_SMT_10MM85_10MM0-MFG]  (value not drawn)
NT1  Net-Tie  [Net-Tie_10mil]  (net tie, no BOM)
R01  value 1m  [FP-KRL3216E-C-R001-J-T5_0612-MFG]  (hidden comment: KRL3216E-C-R001-J-T5)
R02  ValueDisplayed: 9.76k  [0402L]  (hidden comment: CRCW04029K76FKED)
R03  ValueDisplayed: 0  [0402L]  (hidden comment: RK73Z1ETTP)
R04  ValueDisplayed: 10.0k  [0402L]  (hidden comment: RK73H1ETTP1002F)
R05  ValueDisplayed: 0  [0402L]  (hidden comment: RK73Z1ETTP)
R06  ValueDisplayed: 249  [0402L]  (hidden comment: CRCW0402249RFKED)
R07  ValueDisplayed: 54.9k  [0402L]  (hidden comment: CRCW040254K9FKED)
R08  ValueDisplayed: 100k  [0402L]  (hidden comment: CRCW0402100KJNED)
R09  ValueDisplayed: 27.4k  [0402L]  (hidden comment: CRCW040227K4FKED)
R10  ValueDisplayed: 54.9k  [0402L]  (hidden comment: CRCW040254K9FKED)
U01  LMG708B5VBTRQ1  [VBT0022B-MFG]

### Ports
AGND (in), COMP (in), EN/UVLO (in), FB (out), FPWM/SYNC (in), GND (out), IMON (in), ISET (in), PGND (in), SYNCOUT (out), VCC (in), VIN (in), VOUT (out), VSET (in)

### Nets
AGND: C10.2 C23.2 R08.1 R10.1 U01.1(AGND) U01.6(PG) U01.16(AGND) ; port AGND
GND: C01.2 C02.2 C03.2 C04.2 C05.2 C06.2 C07.2 C11.2 C12.2 C13.2 C14.2 C15.2 C16.2 C17.2 C18.1(CATHODE) C19.1(CATHODE) C20.1(CATHODE) C21.2 U01.8(PGND) U01.22(PGND) ; port PGND, port GND
VCC: C10.1 U01.2(VCC) ; port VCC
VIN: C01.1 C02.1 C03.1 C04.1 C05.1 C06.1 C07.1 U01.9(VIN) ; port VIN
VOUT: C11.1 C12.1 C13.1 C14.1 C15.1 C16.1 C17.1 C18.2(ANODE) C19.2(ANODE) C20.2(ANODE) NT1.2 R01.2 R03.2 R07.2 ; port VOUT
BIAS: C21.1 R03.1 U01.3(BIAS)
COMP: U01.21(COMP) ; port COMP
CSA: C22.1 R05.1 R06.1 R09.2 U01.5(CSA)
EN/UVLO: C23.1 U01.11(EN/UVLO) ; port EN/UVLO
FB: U01.20(FB) ; port FB
FPWM/SYNC: U01.13(FPWM/SYNC) ; port FPWM/SYNC
IMON: U01.18(IMON) ; port IMON
ISET: U01.19(ISET) ; port ISET
SW: L01.1 La01.1 R02.1 U01.7(SW)
SYNCOUT: U01.14(SYNCOUT) ; port SYNCOUT
VSET: U01.17(VSET) ; port VSET
NetC09_1: C09.1 R02.2 R04.2 R05.2
NetC09_2: C09.2 C22.2 NT1.1 R04.1 R09.1 U01.4(CSB/VOUT)
NetL01_2: L01.2 La01.2 R01.1 R06.2
NetR07_1: R07.1 R10.2 U01.15(RT)
NetR08_2: R08.2 U01.12(CNFG)

Not connected (* = marked no-connect by the designer): U01 10(NC)*

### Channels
2: designators C01=C201 C02=C202 C03=C203 C04=C204 C05=C205 C06=C206 C07=C207 C09=C209 C10=C210 C11=C211 C12=C212 C13=C213 C14=C214 C15=C215 C16=C216 C17=C217 C18=C218 C19=C219 C20=C220 C21=C221 C22=C222 C23=C223 L01=L201 La01=La201 NT1=NT21 R01=R201 R02=R202 R03=R203 R04=R204 R05=R205 R06=R206 R07=R207 R08=R208 R09=R209 R10=R210 U01=U201; ports AGND=AGND1 COMP=COMP EN/UVLO=EN/UVLO FB=FPWM/SYNC1 FPWM/SYNC=FPWM/SYNC GND=GND IMON=IMON ISET=ISET PGND=GND SYNCOUT=FPWM/SYNC VCC=VCC1 VIN=VFILTER VOUT=VOUT VSET=VSET
3: designators C01=C301 C02=C302 C03=C303 C04=C304 C05=C305 C06=C306 C07=C307 C09=C309 C10=C310 C11=C311 C12=C312 C13=C313 C14=C314 C15=C315 C16=C316 C17=C317 C18=C318 C19=C319 C20=C320 C21=C321 C22=C322 C23=C323 L01=L301 La01=La301 NT1=NT31 R01=R301 R02=R302 R03=R303 R04=R304 R05=R305 R06=R306 R07=R307 R08=R308 R09=R309 R10=R310 U01=U301; ports AGND=AGND1 COMP=COMP EN/UVLO=EN/UVLO FB=FPWM/SYNC1 FPWM/SYNC=FPWM/SYNC GND=GND IMON=IMON ISET=ISET PGND=GND SYNCOUT=FPWM/SYNC VCC=VCC1 VIN=VFILTER VOUT=VOUT VSET=VSET
4: designators C01=C401 C02=C402 C03=C403 C04=C404 C05=C405 C06=C406 C07=C407 C09=C409 C10=C410 C11=C411 C12=C412 C13=C413 C14=C414 C15=C415 C16=C416 C17=C417 C18=C418 C19=C419 C20=C420 C21=C421 C22=C422 C23=C423 L01=L401 La01=La401 NT1=NT41 R01=R401 R02=R402 R03=R403 R04=R404 R05=R405 R06=R406 R07=R407 R08=R408 R09=R409 R10=R410 U01=U401; ports AGND=AGND1 COMP=COMP EN/UVLO=EN/UVLO FB=FPWM/SYNC1 FPWM/SYNC=FPWM/SYNC GND=GND IMON=IMON ISET=ISET PGND=GND SYNCOUT=SYNCOUT_4 VCC=VCC1 VIN=VFILTER VOUT=VOUT VSET=VSET

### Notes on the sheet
- Color key
- Orange indicates configuration options
- Purple gives design/part info
- 48Vin battery (30V-60V) @ 5A/ph
- Black text is labels and miscellaneous notes
- L2 / R(DCR) = R02 * C09
- (near La01) I_L_avg=20A
  I_L_max=26A
- (near La01) Alt. footprint
- 12Vout
  TDC: TBD
  EDC: 25A/ph
- All enabled phases share EN/UVLO with Phase 1
- (near L01) 27Asat
- Cx18-Cx20 are optional
- (near R02) Depop
- Alt. PN: XGL1313-332MED
- (near C09) Depop
- (near R05) Depop
- Depop
- (near R07) Depop
- (near U01) New PN
  LMG708B0
- (near R10) f_sw=400kHz
- (near U01) Top-side pads are GND and SW nodes
- (near R09) Depop
- Each phase has its own VCC and AGND
  (VCC1, VCC2,...)
  (AGND1, AGND2,...)
  Setting up a Port with these Power Port objects enables each instance of this sheet to have its own local instance of the power net (VCC1, VCC2, etc.)
- <default> For shunt sensing:
  Depop Rx02, Cx09, Rx04, Rx05
  For DCR sensing:
  Depop Rx06.
- DRSS ON: Rx07
  DRSS OFF: Rx10 <default>
- Rx09 only needed for dividing down the shunt resistance to slightly increase the peak current limit when using a standard shunt value

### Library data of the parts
C01 C02 C03 = CMP-0082268-1: CAP, CERM, 4.7 µF, 100 V,+/- 10%, X7S, AEC-Q200 Grade 1, 1210; Manufacturer: MuRata; TaMin_C: -55°C; ESR_ohm: 1m; Polarized: N; SizeAreaWB_mm2: 14.7; Value1: 0.001 ohm; U/M: EA; Value: 4.7uF; TaMax_C: 125°C; SizeZ_mm: 2.2; SizeX_mm: 3.2; SizeY_mm: 2.5; Cap_Case: 1210; SizeArea_mm2: 8; AEC Qualified: Y; IRMS_A: 6A; AEC Grade: 1; AEC Category: Q200
C04 = CMP-0007980-2: CAP, CERM, 1 uF, 100 V, +/- 10%, X7S, AEC-Q200 Grade 1, 0805; Manufacturer: TDK; TaMin_C: -55°C; Polarized: N; SizeAreaWB_mm2: 6.75; U/M: EA; Value: 1uF; TaMax_C: 125°C; SizeZ_mm: 1.45; SizeX_mm: 2; SizeY_mm: 1.25; Cap_Case: 0805; SizeArea_mm2: 2.5; AEC Qualified: Y; AEC Grade: 1; AEC Category: Q200; ESR_ohm: 8.255m; IRMS_A: 2.2744A; Value1: 0.008255 ohm
C05 = CMP-0078500-1: CAP, CERM, 0.1 µF,  VAC/100 VDC,+/- 20%, X7R, AEC-Q200 Grade 1, 0603; Manufacturer: Taiyo Yuden; TaMin_C: -55°C; Polarized: N; SizeAreaWB_mm2: 4.68; U/M: EA; Value: 0.1uF; TaMax_C: 125°C; SizeZ_mm: 1; SizeX_mm: 1.6; SizeY_mm: 0.8; Cap_Case: 0603; SizeArea_mm2: 1.28; AEC Qualified: Y; AEC Category: Q200; ValueDisplayed: 0.1µF
C06 = CMP-0006333-2: CAP, CERM, 0.01 uF, 100 V, +/- 10%, X7S, AEC-Q200 Grade 1, 0402; Manufacturer: TDK; TaMin_C: -55°C; Polarized: N; SizeAreaWB_mm2: 3; U/M: EA; Value: 0.01uF; TaMax_C: 125°C; SizeZ_mm: 0.6; SizeX_mm: 1; SizeY_mm: 0.5; Cap_Case: 0402; AEC Qualified: Y; AEC Category: Q200; ESR_ohm: 0.4102; IRMS_A: 291.729mA; Value1: 0.410191 ohm
C07 = CMP-0006332-2: CAP, CERM, 1000 pF, 100 V, +/- 10%, X7S, AEC-Q200 Grade 1, 0402; Manufacturer: TDK; TaMin_C: -55°C; Polarized: N; SizeAreaWB_mm2: 3; U/M: EA; Value: 1000pF; TaMax_C: 125°C; SizeZ_mm: 0.6; SizeX_mm: 1; SizeY_mm: 0.5; Cap_Case: 0402; AEC Qualified: Y; AEC Category: Q200; ESR_ohm: 2.7115; IRMS_A: 264.589mA; Value1: 2.71151 ohm
C09 = CMP-0080610-1: CAP, CERM, 0.1 µF, 25 V,+/- 10%, X7R, AEC-Q200 Grade 1, 0402; Manufacturer: TDK; TaMin_C: -55°C; Polarized: N; SizeAreaWB_mm2: 3; U/M: EA; Value: 0.1uF; TaMax_C: 125°C; SizeZ_mm: 0.6; SizeX_mm: 1; SizeY_mm: 0.5; Cap_Case: 0402; AEC Qualified: Y; AEC Category: Q200; ValueDisplayed: 0.1µF
C10 = CMP-0081052-1: CAP, CERM, 4.7 µF, 16 V,+/- 10%, X5R, AEC-Q200 Grade 3, 0603; Manufacturer: MuRata; SizeAreaWB_mm2: 4.68; SizeArea_mm2: 1.28; AEC Qualified: Y; AEC Category: Q200; Value: 4.7uF; TaMax_C: 85°C; SizeZ_mm: 1; AEC Grade: 3; Polarized: N; TaMin_C: -55°C; SizeY_mm: 0.8; U/M: EA; SizeX_mm: 1.6; Cap_Case: 0603
C11-C17 = CMP-0122305-1: Ceramic Capacitor for Automotive 22uF ±10% 25VDC X7S 1210 Embossed T/R; Manufacturer: Murata; TempCo: 22%; Value: 22µF; SizeZ_mm: 2.85mm; AEC Qualified: Yes; AEC Grade: Grade 1
C18-C20 = CMP-0124500-1: Cap Tant Polymer 150uF 16VDC E CASE 20%( 7.3 X 4.3 X 4.1mm) J Lead SMD 7343-43 0.025 Ohm 125C T/R; Manufacturer: KYOCERA AVX; AEC Grade: Grade 1; AEC Qualified: Yes; Cap_F: 150µF; IRMS_A: 3.162A; SizeZ_mm: 4.3mm; Dissipation Factor: 8%; Esr: 25m; Leakage Current: 240uA; Life: 2000Hours; Value: 150µF
C21 = CMP-0081259-1: CAP, CERM, 1 µF, 35 V,+/- 10%, X7R, AEC-Q200 Grade 1, 0603; Manufacturer: TDK; SizeAreaWB_mm2: 4.68; SizeArea_mm2: 1.28; AEC Qualified: Y; AEC Category: Q200; Value: 1uF; TaMax_C: 125°C; SizeZ_mm: 1; Polarized: N; TaMin_C: -55°C; SizeY_mm: 0.8; U/M: EA; SizeX_mm: 1.6; Cap_Case: 0603
C22 = CMP-0860832-1: CAP, CERM, 47 pF, 50 V,+/- 5%, C0G/NP0, AEC-Q200 Grade 1, 0402; Manufacturer: TDK; TaMax_C: 125°C; AEC Category: Q200; AEC Grade: 1; SizeZ_mm: 0.6; TaMin_C: -55°C; SizeArea_mm2: 0.5; Value: 47pF; AEC Qualified: Y; Polarized: N; U/M: EA; Cap_Case: 0402; SizeAreaWB_mm2: 3
C23 = CMP-0006312-1: CAP, CERM, 47 pF, 50 V, +/- 5%, C0G/NP0, AEC-Q200 Grade 0, 0402; Manufacturer: TDK; TaMin_C: -55°C; Polarized: N; SizeAreaWB_mm2: 3; Value1: Unknown; U/M: EA; Value: 47pF; TaMax_C: 150°C; SizeZ_mm: 0.6; SizeX_mm: 1; SizeY_mm: 0.5; Cap_Case: 0402; AEC Qualified: Y; AEC Grade: 0; AEC Category: Q200
L01 = CMP-0123970-1: Power Choke Coil 4.7uH 20% 100kHz 4.7mOhm 27A AECQ200 13.3x12.8x8.0mm SMT; Manufacturer: Cyntec; AEC Grade: Grade 0; AEC Qualified: Yes; DCR_ohm: 4.7m; Ind_H: 4.7µH; Isat: 23.1A; Material: Metal Dust; SizeZ_mm: 8mm
La01 = CMP-0122346-1: IND SMD 4.7UH AUTO GRADE CHOKE; Manufacturer: Cyntec; AEC Grade: Grade 0; AEC Qualified: Yes; DCR_ohm: 10m; Ind_H: 4.7µH; Irms: 14.5A; Isat: 13.5A; SizeZ_mm: 5.4mm; Shrouded: false; Standoff Height: 0mm; Test Frequency: 100kHz; Tolerance_%: 20%
NT1 = CMP-0078142-4: Single point connection between nets.
R01 = CMP-0124890-1: 1 mOhms ±5% 1.5W Chip Resistor Wide 1206 (3216 Metric), 0612 Automotive AEC-Q200, Current Sense Metal Foil; Manufacturer: Susumu; AEC Grade: Grade 0; AEC Qualified: Yes; SizeZ_mm: 0.7mm; TempCo: 150ppm/°C
R02 = CMP-0026622-3: RES, 9.76 k, 1%, 0.063 W, AEC-Q200 Grade 0, 0402; Manufacturer: Vishay-Dale; AEC Category: Q200; AEC Qualified: Y; AEC Grade: 0; Value2: 0.063W; Value_Code: 9k76; SizeY_mm: 0.5; SizeZ_mm: 0.6; VDC_V: 50V; SizeX_mm: 1; Value: 9.76k; Power_W: 63mW; EIA_Code: E96; TempCo: 100 ppm/C
R03 R05 = CMP-0027007-2: RES, 0, 5%, 0.063 W, AEC-Q200 Grade 0, 0402; Manufacturer: KOA Speer; Power_W: 63mW; TempCo: ppm/C; Value_Code: 0000; Value: 0; EIA_Code: E24; SizeX_mm: 1; SizeZ_mm: 0.6; Value2: 0.063W; SizeArea_mm2: 0.5; AEC Qualified: Y; AEC Category: Q200; U/M: EA
R04 = CMP-0026748-1: RES, 10.0 k, 1%, 0.063 W, AEC-Q200 Grade 0, 0402; Manufacturer: KOA Speer; Power_W: 63mW; TempCo: 100 ppm/C; Value_Code: 10k0; U/M: EA; Value: 10.0k; EIA_Code: E96; Res_ohm: 10k; SizeX_mm: 1; SizeY_mm: 0.5; SizeZ_mm: 0.6; Value2: 0.063W; AEC Qualified: Y; VDC_V: 50V; AEC Grade: 0; AEC Category: Q200
R06 = CMP-0026194-2: RES, 249, 1%, 0.063 W, AEC-Q200 Grade 0, 0402; Manufacturer: Vishay-Dale; Power_W: 63mW; TempCo: 100 ppm/C; Value_Code: 249R; Value: 249; EIA_Code: E96; SizeX_mm: 1; SizeY_mm: 0.5; SizeZ_mm: 0.6; Value2: 0.063W; AEC Qualified: Y; VDC_V: 50V; AEC Category: Q200; AEC Grade: 0
R07 R10 = CMP-0026449-2: RES, 54.9 k, 1%, 0.063 W, AEC-Q200 Grade 0, 0402; Manufacturer: Vishay-Dale; Power_W: 63mW; TempCo: 100 ppm/C; Value_Code: 54k9; Value: 54.9k; EIA_Code: E96; SizeX_mm: 1; SizeY_mm: 0.5; SizeZ_mm: 0.6; Value2: 0.063W; AEC Qualified: Y; VDC_V: 50V; AEC Category: Q200; AEC Grade: 0
R08 = CMP-0026823-3: RES, 100 k, 5%, 0.063 W, AEC-Q200 Grade 0, 0402; Manufacturer: Vishay-Dale; Power_W: 63mW; TempCo: 200 ppm/C; Value: 100k; EIA_Code: E24; SizeX_mm: 1; SizeY_mm: 0.5; SizeZ_mm: 0.6; Value2: 0.063W; AEC Qualified: Y; VDC_V: 50V; AEC Category: Q200; AEC Grade: 0
R09 = CMP-0026213-2: RES, 27.4 k, 1%, 0.063 W, AEC-Q200 Grade 0, 0402; Manufacturer: Vishay-Dale; Power_W: 63mW; TempCo: 100 ppm/C; Value_Code: 27k4; Value: 27.4k; EIA_Code: E96; SizeX_mm: 1; SizeY_mm: 0.5; SizeZ_mm: 0.6; Value2: 0.063W; AEC Qualified: Y; VDC_V: 50V; AEC Category: Q200; AEC Grade: 0
U01 = CMP-0125338-2: Manufacturer: Texas Instruments; SizeZ_mm: 0.85mm; Standoff Height: 0mm; AEC Category: Q200; CompType: IC

## Sheet Phase1.SchDoc
size 431 x 279 mm; Date: Not shown in title block; ApprovedBy: Not shown in title block; CheckedBy: Not shown in title block; Author: Not shown in title block; CompanyName: Not shown in title block; Engineer: Not shown in title block; Organization: Not shown in title block; Address1: Not shown in title block; Address2: Not shown in title block; Address3: Not shown in title block; Address4: Not shown in title block; DocumentNumber: 2; Revision: Use project parameter SCH_Rev; SheetNumber: 2; SheetTotal: 4; PageSetup: Record=PageOptions¦CenterHorizontal=True¦CenterVertical=True¦PrintScale=1.00¦XCorrection=1.00¦YCorrection=1.00¦PrintKind=0¦BorderSize=5000000¦LeftOffset=0¦BottomOffset=0¦Orientation=2¦PaperLength=1000¦PaperWidth=1000¦Scale=100¦PaperSource=15¦PrintQuality=600¦MediaType=1¦DitherType=10¦PaperKind=Letter¦PrintScaleMode=1
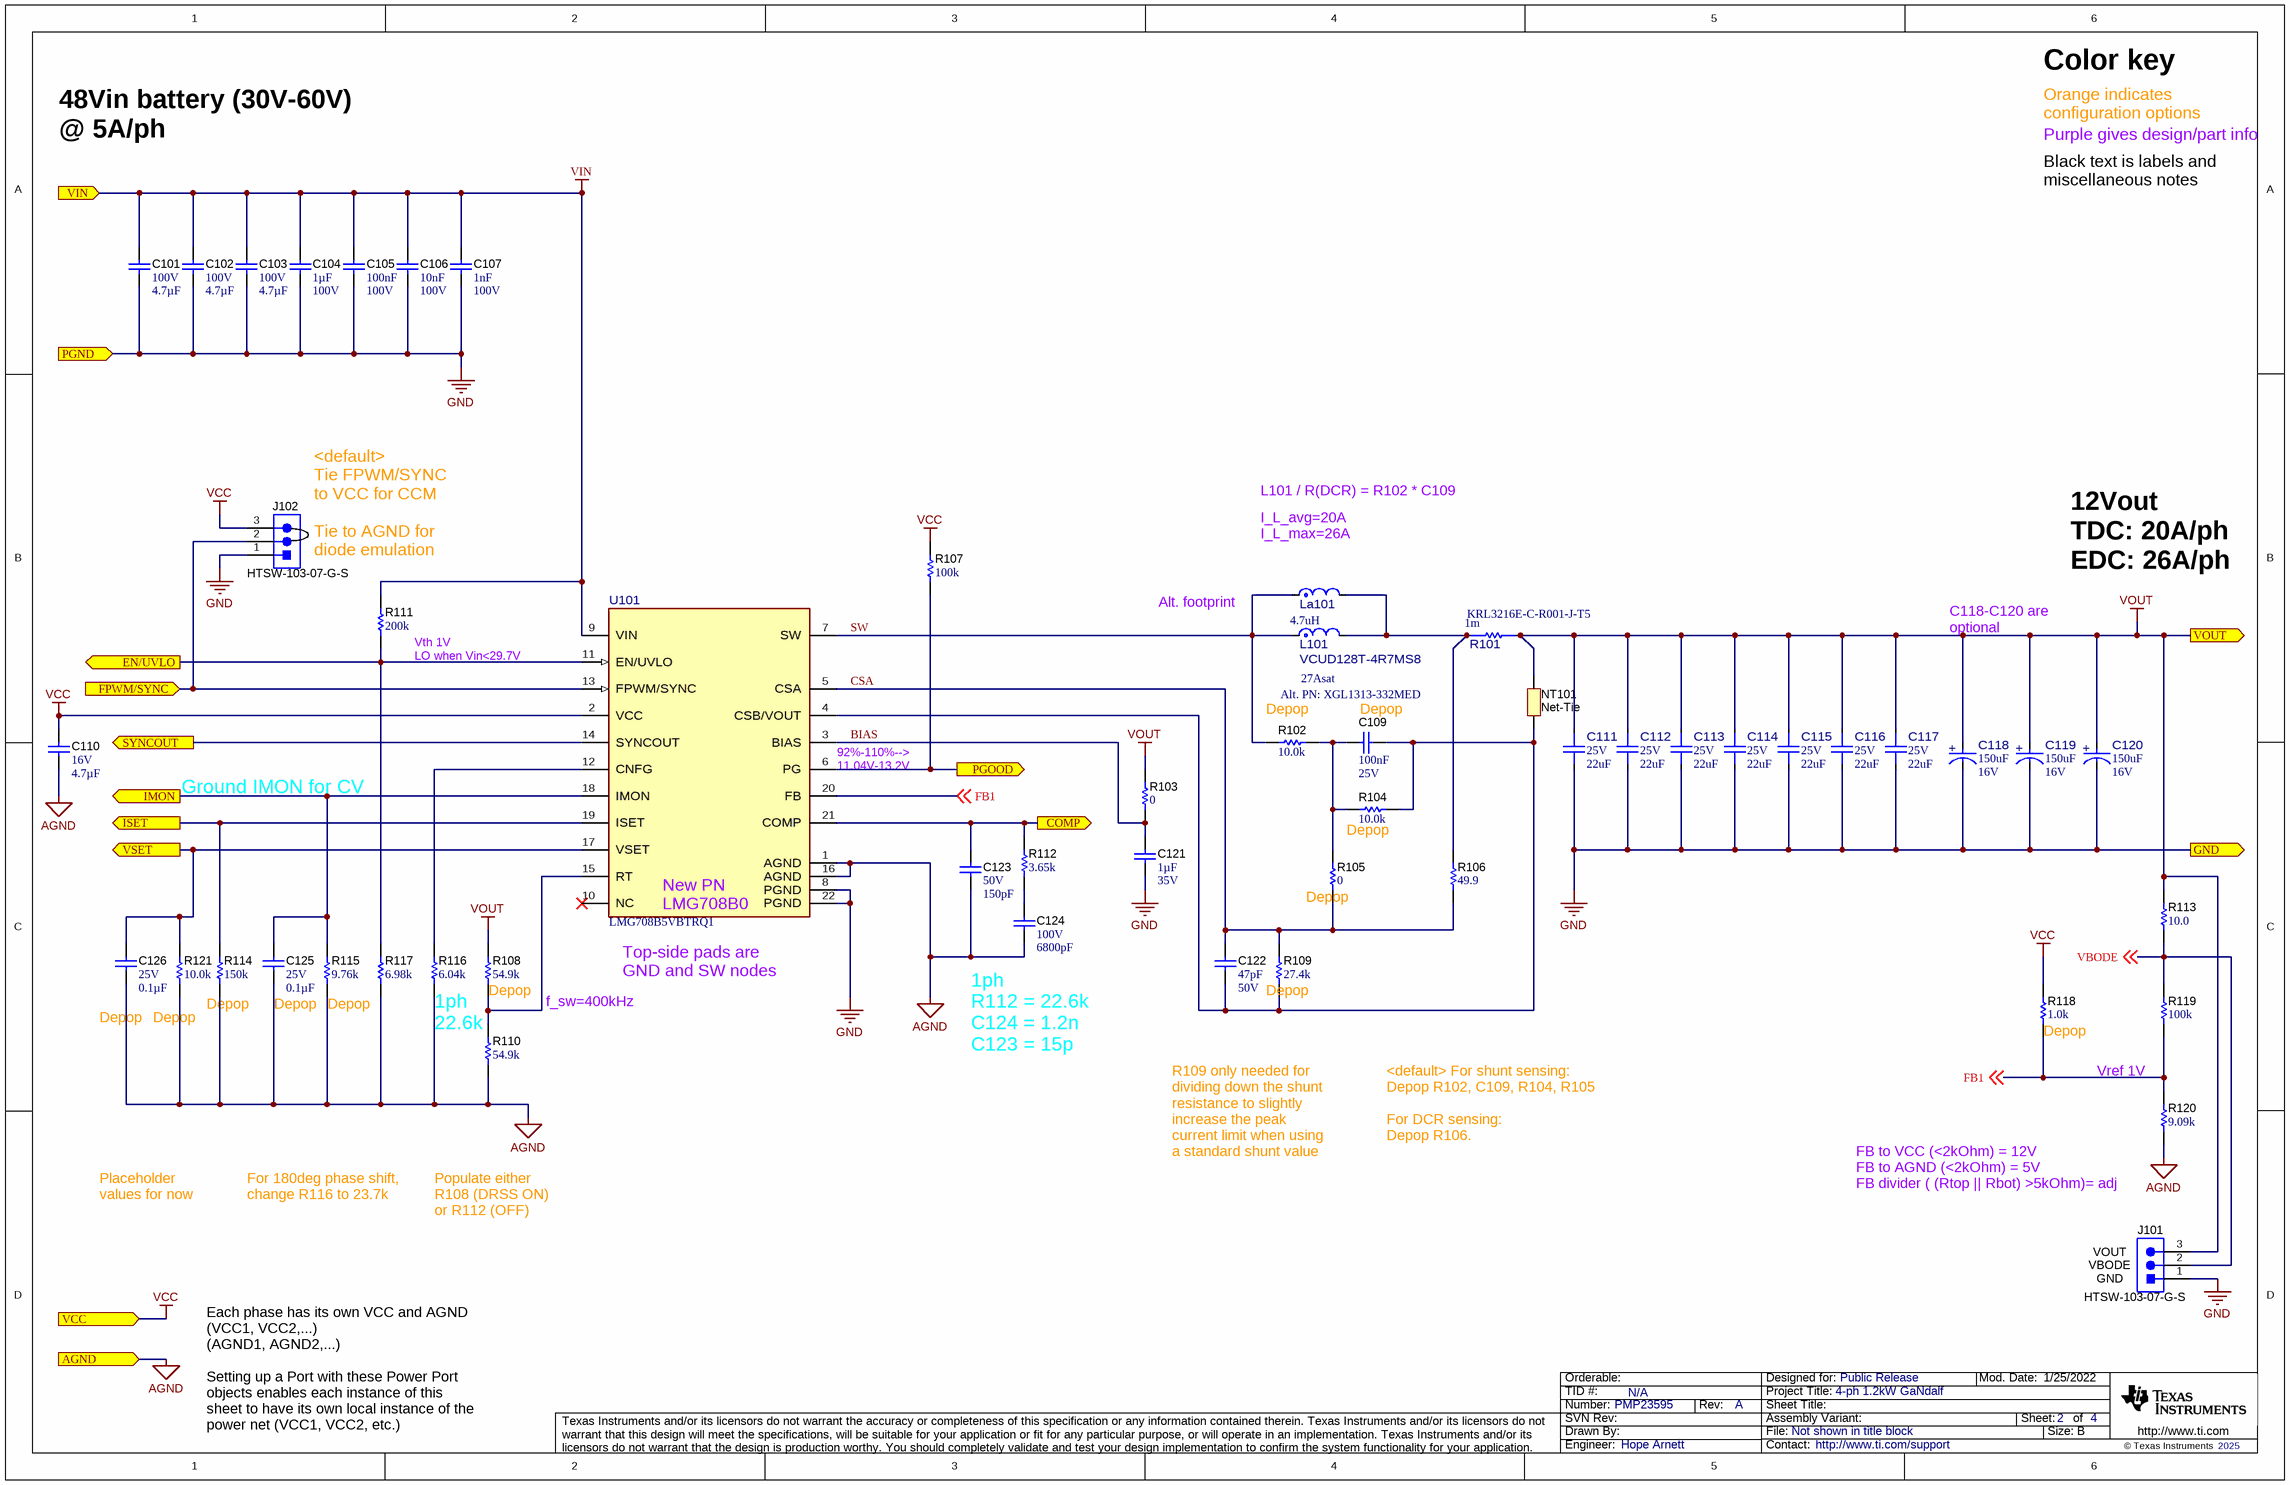
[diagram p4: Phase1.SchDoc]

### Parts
C101  VDC_V: 100V  ValueDisplayed: 4.7µF  [1210_220]  (hidden comment: GCM32DC72A475KE02L)
C102  VDC_V: 100V  ValueDisplayed: 4.7µF  [1210_220]  (hidden comment: GCM32DC72A475KE02L)
C103  VDC_V: 100V  ValueDisplayed: 4.7µF  [1210_220]  (hidden comment: GCM32DC72A475KE02L)
C104  Cap_F: 1µF  VDC_V: 100V  [0805L]  (hidden comment: CGA4J3X7S2A105K125AB)
C105  Cap_F: 100nF  VDC_V: 100V  [0603L]  (hidden comment: HMK107B7104MAHT)
C106  Cap_F: 10nF  VDC_V: 100V  [0402L]  (hidden comment: CGA2B3X7S2A103K050BB)
C107  Cap_F: 1nF  VDC_V: 100V  [0402L]  (hidden comment: CGA2B3X7S2A102K050BB)
C109  Cap_F: 100nF  VDC_V: 25V  [0402L]  (hidden comment: CGA2B3X7R1E104K050BB)
C110  VDC_V: 16V  ValueDisplayed: 4.7µF  [0603L]  (hidden comment: GRT188R61C475KE13D)
C111  VDC_V: 25V  ValueDisplayed: 22uF  [FP-GCM32EC71E226KE36L_1210-MFG]  (hidden comment: GCM32EC71E226KE36L)
C112  VDC_V: 25V  ValueDisplayed: 22uF  [FP-GCM32EC71E226KE36L_1210-MFG]  (hidden comment: GCM32EC71E226KE36L)
C113  VDC_V: 25V  ValueDisplayed: 22uF  [FP-GCM32EC71E226KE36L_1210-MFG]  (hidden comment: GCM32EC71E226KE36L)
C114  VDC_V: 25V  ValueDisplayed: 22uF  [FP-GCM32EC71E226KE36L_1210-MFG]  (hidden comment: GCM32EC71E226KE36L)
C115  VDC_V: 25V  ValueDisplayed: 22uF  [FP-GCM32EC71E226KE36L_1210-MFG]  (hidden comment: GCM32EC71E226KE36L)
C116  VDC_V: 25V  ValueDisplayed: 22uF  [FP-GCM32EC71E226KE36L_1210-MFG]  (hidden comment: GCM32EC71E226KE36L)
C117  VDC_V: 25V  ValueDisplayed: 22uF  [FP-GCM32EC71E226KE36L_1210-MFG]  (hidden comment: GCM32EC71E226KE36L)
C118  ValueDisplayed: 150uF  VDC_V: 16V  [FP-TCQE157M016R0025E_2917-MFG]  (hidden comment: TCQE157M016R0025E)
C119  ValueDisplayed: 150uF  VDC_V: 16V  [FP-TCQE157M016R0025E_2917-MFG]  (hidden comment: TCQE157M016R0025E)
C120  ValueDisplayed: 150uF  VDC_V: 16V  [FP-TCQE157M016R0025E_2917-MFG]  (hidden comment: TCQE157M016R0025E)
C121  Cap_F: 1µF  VDC_V: 35V  [0603L]  (hidden comment: CGA3E1X7R1V105K080AE)
C122  ValueDisplayed: 47pF  VDC_V: 50V  [0402L]  (hidden comment: CGA2B2C0G1H470J050BA)
C123  VDC_V: 50V  ValueDisplayed: 150pF  [0402L]  (hidden comment: CGA2B2C0G1H151J050BA)
C124  VDC_V: 100V  ValueDisplayed: 6800pF  [0402L]  (hidden comment: CGA2B3X7S2A682K050BB)
C125  VDC_V: 25V  ValueDisplayed: 0.1µF  [0402L]  (hidden comment: CGA2B3X7R1E104K050BB)
C126  VDC_V: 25V  ValueDisplayed: 0.1µF  [0402L]  (hidden comment: CGA2B3X7R1E104K050BB)
J101  HTSW-103-07-G-S  [Samtec_HTSW-103-07-G-S]
J102  HTSW-103-07-G-S  [Samtec_HTSW-103-07-G-S]
L101  VCUD128T-4R7MS8  value 4.7uH  [FP-VCUD128T-4R7MS8_SMT_IND_13MM3_12MM8-MFG]
La101  VCHA105D-4R7MS6  [FP-VCHA105D-4R7MS6_SMT_10MM85_10MM0-MFG]  (value not drawn)
NT101  Net-Tie  [Net-Tie_10mil]  (net tie, no BOM)
R101  value 1m  [FP-KRL3216E-C-R001-J-T5_0612-MFG]  (hidden comment: KRL3216E-C-R001-J-T5)
R102  ValueDisplayed: 10.0k  [0402L]  (hidden comment: ERJPA2F1002X)
R103  ValueDisplayed: 0  [0402L]  (hidden comment: RK73Z1ETTP)
R104  ValueDisplayed: 10.0k  [0402L]  (hidden comment: RK73H1ETTP1002F)
R105  ValueDisplayed: 0  [0402L]  (hidden comment: RK73Z1ETTP)
R106  ValueDisplayed: 49.9  [0402L]  (hidden comment: RMCF0402FT49R9)
R107  ValueDisplayed: 100k  [0402L]  (hidden comment: CRCW0402100KJNED)
R108  ValueDisplayed: 54.9k  [0402L]  (hidden comment: CRCW040254K9FKED)
R109  ValueDisplayed: 27.4k  [0402L]  (hidden comment: CRCW040227K4FKED)
R110  ValueDisplayed: 54.9k  [0402L]  (hidden comment: CRCW040254K9FKED)
R111  ValueDisplayed: 200k  [0402L]  (hidden comment: CRCW0402200KJNED)
R112  ValueDisplayed: 3.65k  [0402L]  (hidden comment: CRCW04023K65FKED)
R113  ValueDisplayed: 10.0  [0402L]  (hidden comment: RMCF0402JT10R0)
R114  ValueDisplayed: 150k  [0402L]  (hidden comment: CRCW0402150KJNED)
R115  ValueDisplayed: 9.76k  [0402L]  (hidden comment: CRCW04029K76FKED)
R116  ValueDisplayed: 6.04k  [0402L]  (hidden comment: CRCW04026K04FKED)
R117  ValueDisplayed: 6.98k  [0402L]  (hidden comment: CRCW04026K98FKED)
R118  ValueDisplayed: 1.0k  [0603L]  (hidden comment: ESR03EZPJ102)
R119  ValueDisplayed: 100k  [0603L]  (hidden comment: CRCW0603100KFKEA)
R120  ValueDisplayed: 9.09k  [0603L]  (hidden comment: CRCW06039K09FKEA)
R121  ValueDisplayed: 10.0k  [0402L]  (hidden comment: RK73H1ETTP1002F)
U101  LMG708B5VBTRQ1  [VBT0022B-MFG]

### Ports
AGND (in), COMP (out), EN/UVLO (out), FPWM/SYNC (in), GND (out), IMON (out), ISET (out), PGND (in), PGOOD (out), SYNCOUT (out), VCC (in), VIN (in), VOUT (out), VSET (out)

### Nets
AGND: C110.2 C123.2 C124.2 C125.2 C126.2 R110.1 R114.1 R115.1 R116.1 R117.1 R120.1 R121.1 U101.1(AGND) U101.16(AGND) ; port AGND  [project net AGND1]
GND: C101.2 C102.2 C103.2 C104.2 C105.2 C106.2 C107.2 C111.2 C112.2 C113.2 C114.2 C115.2 C116.2 C117.2 C118.1(CATHODE) C119.1(CATHODE) C120.1(CATHODE) C121.2 J101.1 J102.1 U101.8(PGND) U101.22(PGND) ; port PGND, port GND
VCC: C110.1 J102.3 R107.2 R118.2 U101.2(VCC) ; port VCC  [project net VCC1]
VIN: C101.1 C102.1 C103.1 C104.1 C105.1 C106.1 C107.1 R111.2 U101.9(VIN) ; port VIN  [project net VFILTER]
VOUT: C111.1 C112.1 C113.1 C114.1 C115.1 C116.1 C117.1 C118.2(ANODE) C119.2(ANODE) C120.2(ANODE) J101.3 NT101.2 R101.2 R103.2 R108.2 R113.2 ; port VOUT
BIAS: C121.1 R103.1 U101.3(BIAS)
COMP: C123.1 R112.2 U101.21(COMP) ; port COMP
CSA: C122.1 R105.1 R106.1 R109.2 U101.5(CSA)
EN/UVLO: R111.1 R117.2 U101.11(EN/UVLO) ; port EN/UVLO
FB1: R118.1 R119.1 R120.2 U101.20(FB) ; off-sheet FB1
FPWM/SYNC: U101.14(SYNCOUT) ; port SYNCOUT
FPWM/SYNC1: J102.2 U101.13(FPWM/SYNC) ; port FPWM/SYNC
IMON: C125.1 R115.2 U101.18(IMON) ; port IMON
ISET: R114.2 U101.19(ISET) ; port ISET
PGOOD: R107.1 U101.6(PG) ; port PGOOD
SW: L101.1 La101.1 R102.1 U101.7(SW)
VBODE: J101.2 R113.1 R119.2 ; off-sheet VBODE
VSET: C126.1 R121.2 U101.17(VSET) ; port VSET
NetC109_1: C109.1 R102.2 R104.2 R105.2
NetC109_2: C109.2 C122.2 NT101.1 R104.1 R109.1 U101.4(CSB/VOUT)
NetC124_1: C124.1 R112.1
NetL101_2: L101.2 La101.2 R101.1 R106.2
NetR108_1: R108.1 R110.2 U101.15(RT)
NetR116_2: R116.2 U101.12(CNFG)

Not connected (* = marked no-connect by the designer): U101 10(NC)*

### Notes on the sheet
- Color key
- 48Vin battery (30V-60V) @ 5A/ph
- Orange indicates configuration options
- Purple gives design/part info
- Black text is labels and miscellaneous notes
- L101 / R(DCR) = R102 * C109
- <default>
  Tie FPWM/SYNC to VCC for CCM
  Tie to AGND for diode emulation
- (near La101) I_L_avg=20A
  I_L_max=26A
- Alt. footprint
- C118-C120 are optional
- 12Vout
  TDC: 20A/ph
  EDC: 26A/ph
- Vth 1V
  LO when Vin<29.7V
- Alt. PN: XGL1313-332MED
- (near L101) 27Asat
- (near U101) 92%-110%-->
  11.04V-13.2V
- (near R102) Depop
- (near C109) Depop
- Ground IMON for CV
- (near R104) Depop
- (near R105) Depop
- (near U101) New PN
  LMG708B0
- Depop
- (near R114) Depop
- (near R115) Depop
- 1ph
  22.6k
- (near R108) Depop
- f_sw=400kHz
- (near U101) Top-side pads are GND and SW nodes
- (near R109) Depop
- (near R118) Depop
- (near C124) 1ph
  R112 = 22.6k
  C124 = 1.2n
  C123 = 15p
- (near R120) Vref 1V
- R109 only needed for dividing down the shunt resistance to slightly increase the peak current limit when using a standard shunt value
- <default> For shunt sensing:
  Depop R102, C109, R104, R105
  For DCR sensing:
  Depop R106.
- Placeholder values for now
  Make R121 150R
- For 180deg phase shift, change R116 to 23.7k
- Populate either R108 (DRSS ON) or R112 (OFF)
- FB to VCC (<2kOhm) = 12V
  FB to AGND (<2kOhm) = 5V
  FB divider ( (Rtop || Rbot) >5kOhm)= adj
- (near J101) VOUT
- (near J101) VBODE
- (near J101) GND
- Each phase has its own VCC and AGND
  (VCC1, VCC2,...)
  (AGND1, AGND2,...)
  Setting up a Port with these Power Port objects enables each instance of this sheet to have its own local instance of the power net (VCC1, VCC2, etc.)

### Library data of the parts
C101-C103 = CMP-0082268-1: as C01 on sheet ModularPhases
C104 = CMP-0007980-2: as C04 on sheet ModularPhases
C105 = CMP-0078500-1: as C05 on sheet ModularPhases
C106 = CMP-0006333-2: as C06 on sheet ModularPhases
C107 = CMP-0006332-2: as C07 on sheet ModularPhases
C109 = CMP-0080610-1: as C09 on sheet ModularPhases
C110 = CMP-0081052-1: as C10 on sheet ModularPhases
C111-C117 = CMP-0122305-1: as C11 on sheet ModularPhases
C118-C120 = CMP-0124500-1: as C18 on sheet ModularPhases
C121 = CMP-0081259-1: as C21 on sheet ModularPhases
C122 = CMP-0860832-1: as C22 on sheet ModularPhases
C123 = CMP-0006310-1: CAP, CERM, 150 pF, 50 V, +/- 5%, C0G/NP0, AEC-Q200 Grade 1, 0402; Manufacturer: TDK; TaMin_C: -55°C; Polarized: N; SizeAreaWB_mm2: 3; Value1: Unknown; U/M: EA; Value: 150pF; TaMax_C: 125°C; SizeZ_mm: 0.6; SizeX_mm: 1; SizeY_mm: 0.5; Cap_Case: 0402; AEC Qualified: Y; AEC Category: Q200
C124 = CMP-0006338-2: CAP, CERM, 6800 pF, 100 V, +/- 10%, X7S, AEC-Q200 Grade 1, 0402; Manufacturer: TDK; TaMin_C: -55°C; ESR_ohm: 0.5232; Polarized: N; SizeAreaWB_mm2: 3; Value1: 0.523223 ohm; U/M: EA; Value: 6800pF; TaMax_C: 125°C; SizeZ_mm: 0.6; SizeX_mm: 1; SizeY_mm: 0.5; Cap_Case: 0402; AEC Qualified: Y; Cap_F: 6.8nF; IRMS_A: 273.561mA; AEC Category: Q200
C125 C126 = CMP-0080610-1: CAP, CERM, 0.1 µF, 25 V,+/- 10%, X7R, AEC-Q200 Grade 1, 0402; Manufacturer: TDK; TaMin_C: -55°C; Polarized: N; SizeAreaWB_mm2: 3; U/M: EA; Value: 0.1uF; TaMax_C: 125°C; SizeZ_mm: 0.6; SizeX_mm: 1; SizeY_mm: 0.5; Cap_Case: 0402; AEC Qualified: Y; Cap_F: 100nF; AEC Category: Q200
J101 J102 = CMP-0075484-1: Header, 100mil, 3x1, Gold, TH; Manufacturer: Samtec; Green_REACh: Passed; CT: False; Green_Lifecycle: Active; CNHeader: True
L101 = CMP-0123970-1: as L01 on sheet ModularPhases
La101 = CMP-0122346-1: as La01 on sheet ModularPhases
NT101 = CMP-0078142-4: Single point connection between nets.
R101 = CMP-0124890-1: as R01 on sheet ModularPhases
R102 = CMP-0078779-1: RES, 10.0 k, 1%, 0.2 W, AEC-Q200 Grade 0, 0402; Manufacturer: Panasonic; Power_W: 200mW; TempCo: 100 ppm/C; Value_Code: 10k0; Value: 10.0k; EIA_Code: E96; Res_ohm: 10k; SizeX_mm: 1; SizeY_mm: 0.5; SizeZ_mm: 0.6; Value2: 0.2W; AEC Qualified: Y; AEC Grade: 0; AEC Category: Q200; VDC_V: 50V
R103 R105 = CMP-0027007-2: as R03 on sheet ModularPhases
R104 R121 = CMP-0026748-1: as R04 on sheet ModularPhases
R106 = CMP-0026761-1: RES, 49.9, 1%, 0.063 W, AEC-Q200 Grade 0, 0402; Manufacturer: Stackpole Electronics Inc; Power_W: 63mW; TempCo: 100 ppm/C; Value_Code: 49R9; U/M: EA; Value: 49.9; EIA_Code: E96; SizeX_mm: 1; SizeY_mm: 0.5; SizeZ_mm: 0.6; Value2: 0.063W; AEC Qualified: Y; VDC_V: 50V; AEC Grade: 0; AEC Category: Q200
R107 = CMP-0026823-3: RES, 100 k, 5%, 0.063 W, AEC-Q200 Grade 0, 0402; Manufacturer: Vishay-Dale; Power_W: 63mW; TempCo: 200 ppm/C; Value: 100k; EIA_Code: E24; SizeX_mm: 1; SizeY_mm: 0.5; SizeZ_mm: 0.6; Value2: 0.063W; AEC Qualified: Y; VDC_V: 50V; AEC Grade: 0; AEC Category: Q200
R108 R110 = CMP-0026449-2: as R07 on sheet ModularPhases
R109 = CMP-0026213-2: as R09 on sheet ModularPhases
R111 = CMP-0026873-2: RES, 200 k, 5%, 0.063 W, AEC-Q200 Grade 0, 0402; Manufacturer: Vishay-Dale; Power_W: 63mW; TempCo: 200 ppm/C; Value: 200k; EIA_Code: E24; SizeX_mm: 1; SizeY_mm: 0.5; SizeZ_mm: 0.6; Value2: 0.063W; AEC Qualified: Y; VDC_V: 50V; AEC Category: Q200; AEC Grade: 0
R112 = CMP-0026337-2: RES, 3.65 k, 1%, 0.063 W, AEC-Q200 Grade 0, 0402; Manufacturer: Vishay-Dale; Power_W: 63mW; TempCo: 100 ppm/C; Value_Code: 3k65; Value: 3.65k; EIA_Code: E96; SizeX_mm: 1; SizeY_mm: 0.5; SizeZ_mm: 0.6; Value2: 0.063W; AEC Qualified: Y; VDC_V: 50V; AEC Category: Q200; AEC Grade: 0
R113 = CMP-0026764-1: RES, 10.0, 1%, 0.063 W, AEC-Q200 Grade 0, 0402; Manufacturer: Stackpole Electronics Inc; Power_W: 63mW; TempCo: 100 ppm/C; Value_Code: 10R0; Value: 10.0; EIA_Code: E96; Res_ohm: 10; SizeX_mm: 1; SizeY_mm: 0.5; SizeZ_mm: 0.6; Value2: 0.063W; AEC Qualified: Y; AEC Grade: 0; AEC Category: Q200; U/M: EA
R114 = CMP-0026840-2: RES, 150 k, 5%, 0.063 W, AEC-Q200 Grade 0, 0402; Manufacturer: Vishay-Dale; Power_W: 63mW; TempCo: 200 ppm/C; Value: 150k; EIA_Code: E24; SizeX_mm: 1; SizeY_mm: 0.5; SizeZ_mm: 0.6; Value2: 0.063W; AEC Qualified: Y; VDC_V: 50V; AEC Category: Q200; AEC Grade: 0
R115 = CMP-0026622-3: as R02 on sheet ModularPhases
R116 = CMP-0026512-2: RES, 6.04 k, 1%, 0.063 W, AEC-Q200 Grade 0, 0402; Manufacturer: Vishay-Dale; Power_W: 63mW; TempCo: 100 ppm/C; Value_Code: 6k04; Value: 6.04k; EIA_Code: E96; SizeX_mm: 1; SizeY_mm: 0.5; SizeZ_mm: 0.6; Value2: 0.063W; AEC Qualified: Y; VDC_V: 50V; AEC Category: Q200; AEC Grade: 0
R117 = CMP-0026518-2: RES, 6.98 k, 1%, 0.063 W, AEC-Q200 Grade 0, 0402; Manufacturer: Vishay-Dale; Power_W: 63mW; TempCo: 100 ppm/C; Value_Code: 6k98; Value: 6.98k; EIA_Code: E96; SizeX_mm: 1; SizeY_mm: 0.5; SizeZ_mm: 0.6; Value2: 0.063W; AEC Qualified: Y; VDC_V: 50V; AEC Category: Q200; AEC Grade: 0
R118 = CMP-0084244-1: RES, 1.0 k, 5%, 0.25 W, AEC-Q200 Grade 0, 0603; Manufacturer: Rohm; Power_W: 250mW; TempCo: 200 ppm/C; SizeAreaWB_mm2: 4.68; Value_Code: 1k00; Value: 1.0k; EIA_Code: E24; Res_ohm: 1k; SizeX_mm: 1.6; SizeY_mm: 0.8; SizeZ_mm: 1; Value2: 0.25W; SizeArea_mm2: 1.28; AEC Qualified: Y; AEC Grade: 0; AEC Category: Q200
R119 = CMP-0021990-4: RES, 100 k, 1%, 0.1 W, AEC-Q200 Grade 0, 0603; Manufacturer: Vishay-Dale; Power_W: 100mW; TempCo: 100 ppm/C; Value: 100k; EIA_Code: E96; SizeX_mm: 1.6; SizeY_mm: 0.8; SizeZ_mm: 1; Value2: 0.1W; SizeArea_mm2: 1.28; AEC Qualified: Y; VDC_V: 75V; AEC Category: Q200; AEC Grade: 0
R120 = CMP-0022665-4: RES, 9.09 k, 1%, 0.1 W, AEC-Q200 Grade 0, 0603; Manufacturer: Vishay-Dale; Power_W: 100mW; TempCo: 100 ppm/C; Value_Code: 9k09; Value: 9.09k; EIA_Code: E96; SizeX_mm: 1.6; SizeY_mm: 0.8; SizeZ_mm: 1; Value2: 0.1W; SizeArea_mm2: 1.28; AEC Qualified: Y; VDC_V: 75V; AEC Category: Q200; AEC Grade: 0
U101 = CMP-0125338-2: as U01 on sheet ModularPhases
